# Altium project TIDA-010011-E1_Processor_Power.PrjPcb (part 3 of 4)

## Sheet TIDA-010011-E1_Processor_Power _Pg7.SchDoc: POINT OF LOAD
size 431 x 279 mm; Date: Not shown in title block; ApprovedBy: Not shown in title block; CheckedBy: Not shown in title block; Author: Not shown in title block; CompanyName: Not shown in title block; DrawnBy: Sreenivasa; Engineer: Not shown in title block; Organization: Not shown in title block; Address1: Not shown in title block; Address2: Not shown in title block; Address3: Not shown in title block; Address4: Not shown in title block; DocumentNumber: 1; Revision: Use project parameter SCH_Rev; SheetNumber: 7; SheetTotal: 12; PageSetup: Record=PageOptions¦CenterHorizontal=True¦CenterVertical=True¦PrintScale=0.62¦XCorrection=1.00¦YCorrection=1.00¦PrintKind=0¦BorderSize=5000000¦LeftOffset=0¦BottomOffset=0¦Orientation=2¦PaperLength=1000¦PaperWidth=1000¦Scale=100¦PaperSource=15¦PrintQuality=600¦MediaType=1¦DitherType=10¦PrintScaleMode=1¦PaperKind=Letter
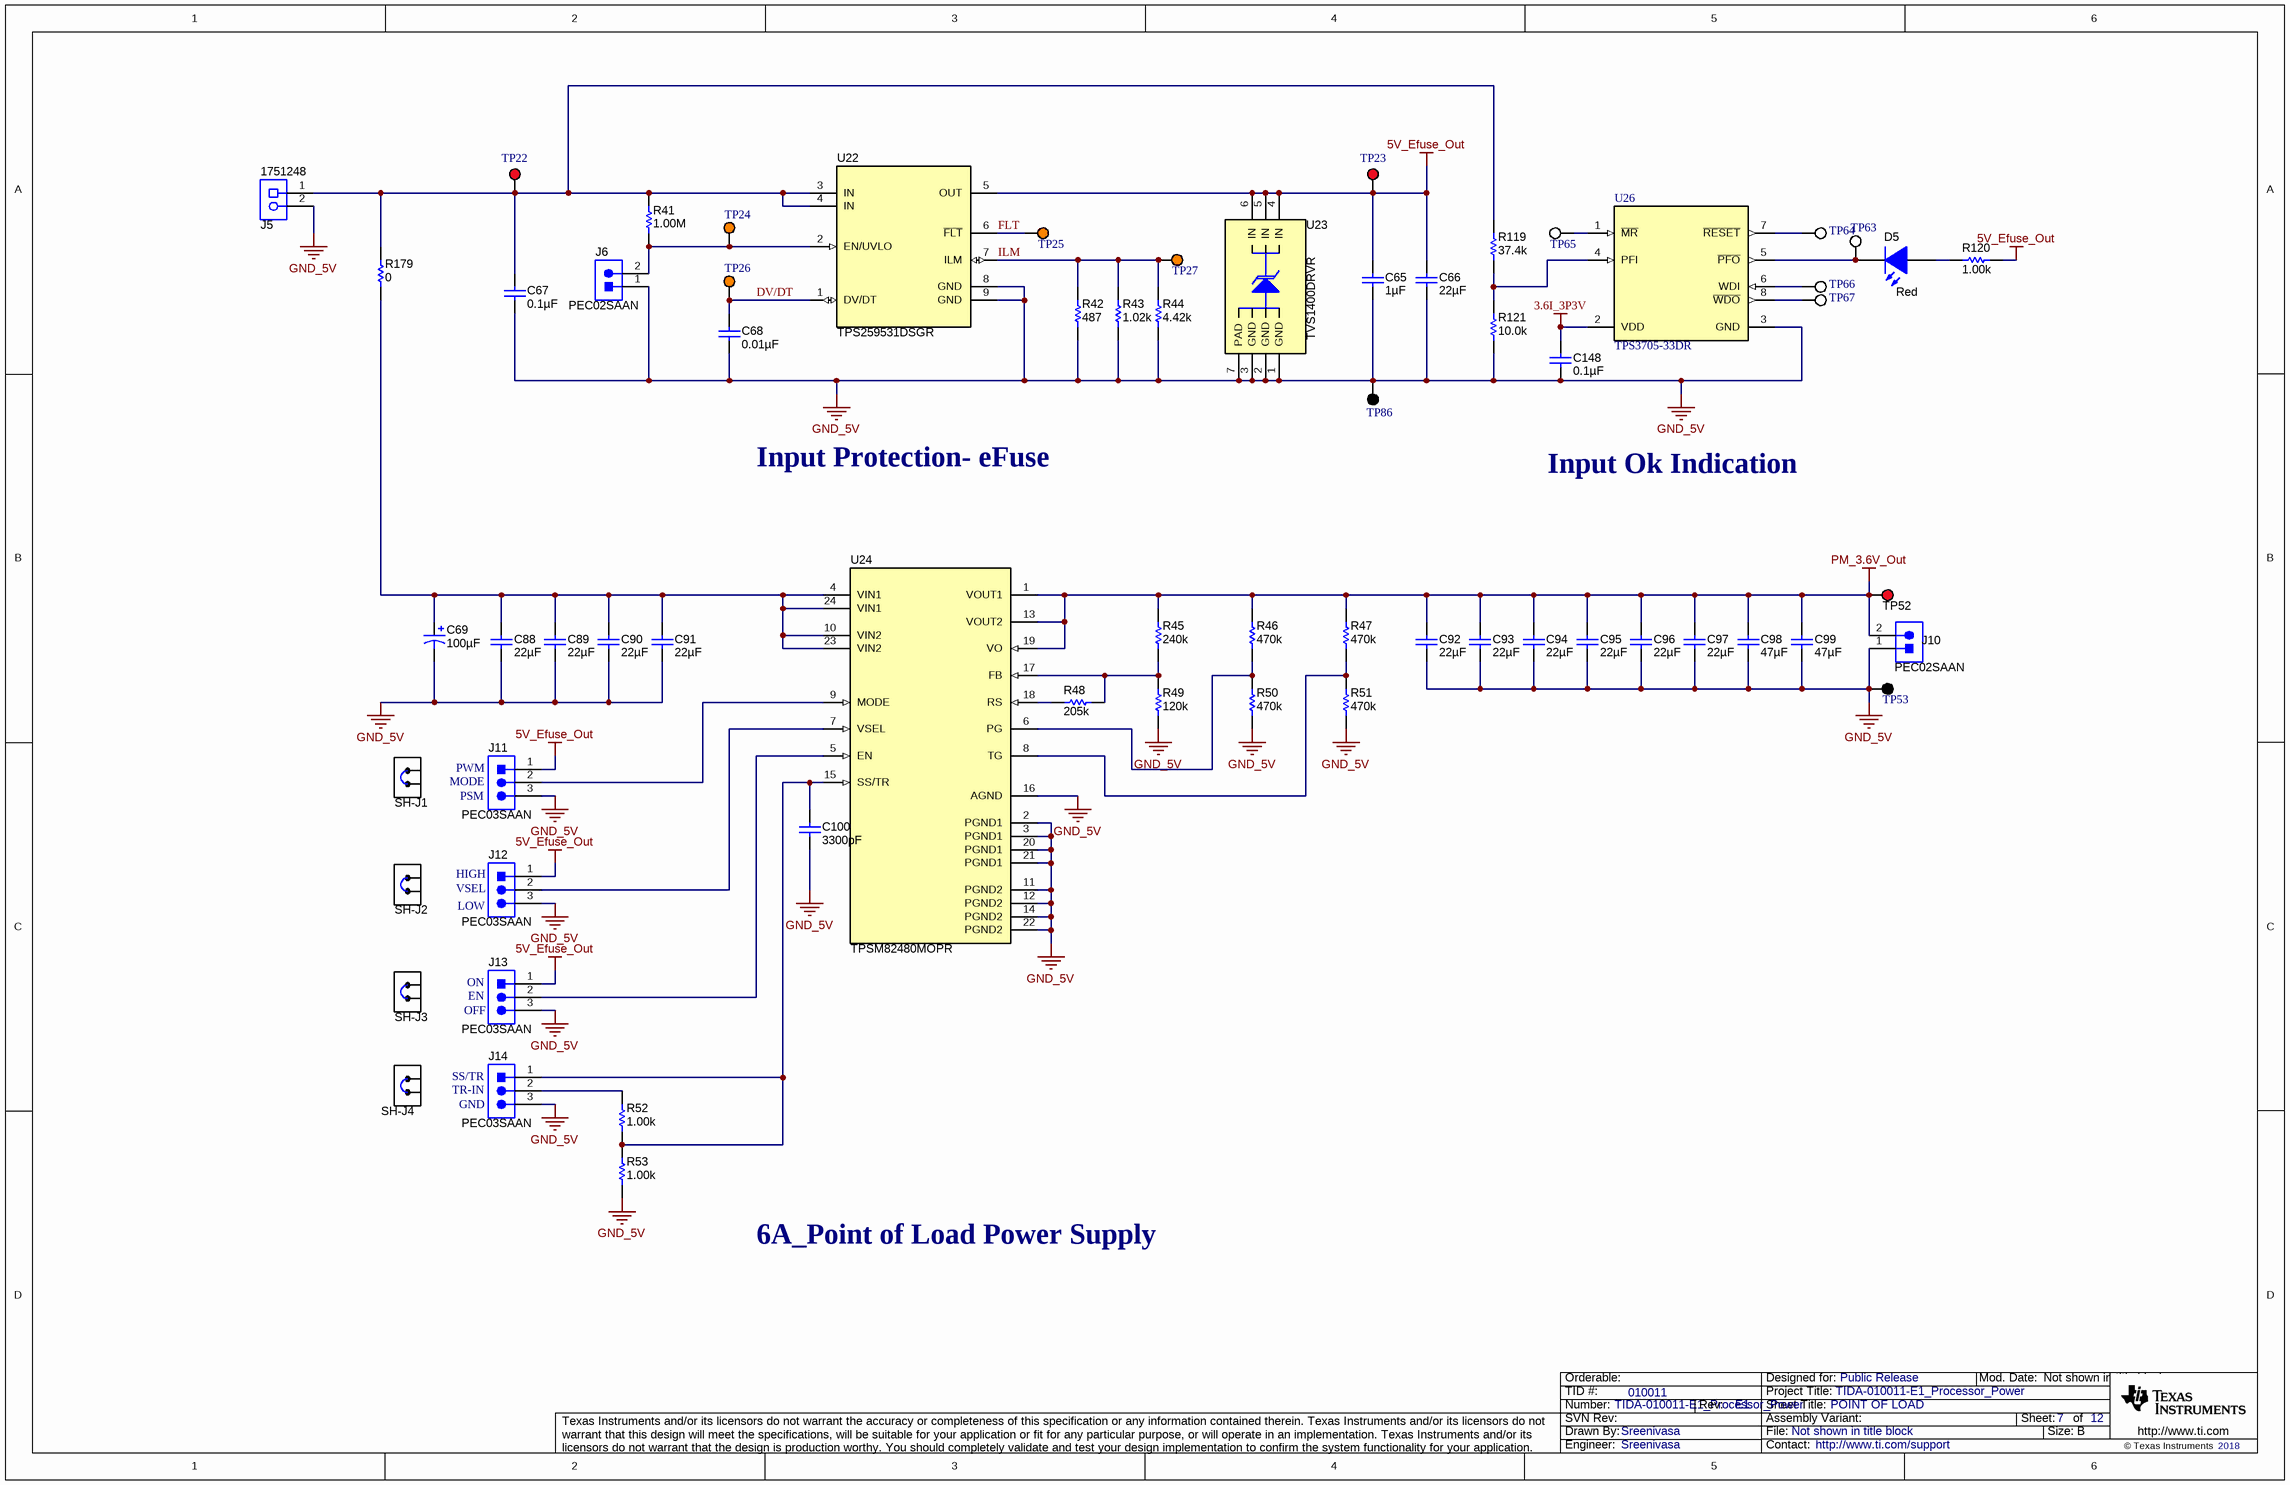
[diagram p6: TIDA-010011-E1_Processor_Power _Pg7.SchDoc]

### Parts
C65  ValueDisplayed: 1µF  [0805_HV]  (hidden comment: 08053D105KAT2A)
C66  ValueDisplayed: 22µF  [1812_280]  (hidden comment: C4532X5R1E226M250KA)
C67  ValueDisplayed: 0.1µF  [0603]  (hidden comment: GRM188R71E104KA01D)
C68  ValueDisplayed: 0.01µF  [0603]  (hidden comment: GRM188R71E103KA01D)
C69  ValueDisplayed: 100µF  [7343-43]  (hidden comment: 293D107X9020E2TE3)
C88  ValueDisplayed: 22µF  [0603]  (hidden comment: GRM188R61A226ME15D)
C89  ValueDisplayed: 22µF  [0603]  (hidden comment: GRM188R61A226ME15D)
C90  ValueDisplayed: 22µF  [0603]  (hidden comment: GRM188R61A226ME15D)
C91  ValueDisplayed: 22µF  [0603]  (hidden comment: GRM188R61A226ME15D)
C92  ValueDisplayed: 22µF  [0805_HV]  (hidden comment: GRM21BR61E226ME44L)
C93  ValueDisplayed: 22µF  [0805_HV]  (hidden comment: GRM21BR61E226ME44L)
C94  ValueDisplayed: 22µF  [0805_HV]  (hidden comment: GRM21BR61E226ME44L)
C95  ValueDisplayed: 22µF  [0805_HV]  (hidden comment: GRM21BR61E226ME44L)
C96  ValueDisplayed: 22µF  [0805_HV]  (hidden comment: GRM21BR61E226ME44L)
C97  ValueDisplayed: 22µF  [0805_HV]  (hidden comment: GRM21BR61E226ME44L)
C98  ValueDisplayed: 47µF  [CKG57N]  (hidden comment: CKG57NX7S1E476M500JH)
C99  ValueDisplayed: 47µF  [CKG57N]  (hidden comment: CKG57NX7S1E476M500JH)
C100  ValueDisplayed: 3300pF  [0603]  (hidden comment: GRM188R71H332KA01D)
C148  ValueDisplayed: 0.1µF  [0603]  (hidden comment: GRM188R71E104KA01D)
D5  value Red  [LED_LTST-C170_Red]  (hidden comment: CMP-0002829-2)
J5  1751248  [CONN_1751248]
J6  PEC02SAAN  [CONN_PEC02SAAN]
J10  PEC02SAAN  [CONN_PEC02SAAN]
J11  PEC03SAAN  [CONN_PEC03SAAN]
J12  PEC03SAAN  [CONN_PEC03SAAN]
J13  PEC03SAAN  [CONN_PEC03SAAN]
J14  PEC03SAAN  [CONN_PEC03SAAN]
R41  ValueDisplayed: 1.00M  [0603]  (hidden comment: CRCW06031M00FKEA)
R42  ValueDisplayed: 487  [0603]  (hidden comment: CRCW0603487RFKEA)
R43  ValueDisplayed: 1.02k  [0603]  (hidden comment: RC0603FR-071K02L)
R44  ValueDisplayed: 4.42k  [0603]  (hidden comment: CRCW06034K42FKEA)
R45  ValueDisplayed: 240k  [0603]  (hidden comment: RC0603FR-07240KL)
R46  ValueDisplayed: 470k  [0603]  (hidden comment: RC0603FR-07470KL)
R47  ValueDisplayed: 470k  [0603]  (hidden comment: RC0603FR-07470KL)
R48  ValueDisplayed: 205k  [0603]  (hidden comment: CRCW0603205KFKEA)
R49  ValueDisplayed: 120k  [0603]  (hidden comment: RC0603FR-07120KL)
R50  ValueDisplayed: 470k  [0603]  (hidden comment: RC0603FR-07470KL)
R51  ValueDisplayed: 470k  [0603]  (hidden comment: RC0603FR-07470KL)
R52  ValueDisplayed: 1.00k  [0603]  (hidden comment: RC0603FR-071KL)
R53  ValueDisplayed: 1.00k  [0603]  (hidden comment: RC0603FR-071KL)
R119  ValueDisplayed: 37.4k  [0603]  (hidden comment: CRCW060337K4FKEA)
R120  ValueDisplayed: 1.00k  [0603]  (hidden comment: ERJ-3EKF1001V)
R121  ValueDisplayed: 10.0k  [0603]  (hidden comment: CRCW060310K0FKEA)
R179  ValueDisplayed: 0  [0805_HV]  (hidden comment: CRCW08050000Z0EA)
SH-J1  881545-2  [TE_881545-2]  (value not drawn)  (mechanical)
SH-J2  881545-2  [TE_881545-2]  (value not drawn)  (mechanical)
SH-J3  881545-2  [TE_881545-2]  (value not drawn)  (mechanical)
SH-J4  881545-2  [TE_881545-2]  (value not drawn)  (mechanical)
TP22  5000  [Keystone5000]  (value not drawn)
TP23  5000  [Keystone5000]  (value not drawn)
TP24  5003  [Keystone5003]  (value not drawn)
TP25  5003  [Keystone5003]  (value not drawn)
TP26  5003  [Keystone5003]  (value not drawn)
TP27  5003  [Keystone5003]  (value not drawn)
TP52  (no value)  [Keystone5000]
TP53  5001  [Keystone5001]  (value not drawn)
TP63  5002  [Keystone5002]  (value not drawn)
TP64  5002  [Keystone5002]  (value not drawn)
TP65  5002  [Keystone5002]  (value not drawn)
TP66  5002  [Keystone5002]  (value not drawn)
TP67  5002  [Keystone5002]  (value not drawn)
TP86  5001  [Keystone5001]  (value not drawn)
U22  TPS259531DSGR  [DSG0008A]
U23  TVS1400DRVR  [DRV0006A]
U24  TPSM82480MOPR  [MOP0024A]
U26  TPS3705-33DR  [D0008A_N]

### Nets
3.6I_3P3V: C148.1 U26.2(VDD)
5V_Efuse_Out: C65.1 C66.1 J11.1 J12.1 J13.1 R120.2 TP23.1 U22.5(OUT) U23.4(IN) U23.5(IN) U23.6(IN)
GND_5V: C65.2 C66.2 C67.2 C68.2 C69.2(-) C88.2 C89.2 C90.2 C91.2 C92.2 C93.2 C94.2 C95.2 C96.2 C97.2 C98.2 C99.2 C100.1 C148.2 J5.2 J6.1 J10.1 J11.3 J12.3 J13.3 J14.3 R42.1 R43.1 R44.1 R49.1 R50.1 R51.1 R53.1 R121.1 TP53.1 TP86.1 U22.8(GND) U22.9(GND) U23.1(GND) U23.2(GND) U23.3(GND) U23.7(PAD) U24.2(PGND1) U24.3(PGND1) U24.11(PGND2) U24.12(PGND2) U24.14(PGND2) U24.16(AGND) U24.20(PGND1) U24.21(PGND1) U24.22(PGND2) U26.3(GND)
PM_3.6V_Out: C92.1 C93.1 C94.1 C95.1 C96.1 C97.1 C98.1 C99.1 J10.2 R45.2 R46.2 R47.2 TP52.1 U24.1(VOUT1) U24.13(VOUT2) U24.19(VO)
DV/DT: C68.1 TP26.1 U22.1(DV/DT)
FLT: TP25.1 U22.6(~{FLT})
ILM: R42.2 R43.2 R44.2 TP27.1 U22.7(ILM)
NetC67_1: C67.1 J5.1 R41.2 R119.2 R179.1 TP22.1 U22.3(IN) U22.4(IN)
NetC69_1: C69.1(+) C88.1 C89.1 C90.1 C91.1 R179.2 U24.4(VIN1) U24.10(VIN2) U24.23(VIN2) U24.24(VIN1)
NetC100_2: C100.2 J14.1 R52.1 R53.2 U24.15(SS/TR)
NetD5_1: D5.1(A) R120.1
NetD5_2: D5.2(K) TP63.1 U26.5(~{PFO})
NetJ6_2: J6.2 R41.1 TP24.1 U22.2(EN/UVLO)
NetJ11_2: J11.2 U24.9(MODE)
NetJ12_2: J12.2 U24.7(VSEL)
NetJ13_2: J13.2 U24.5(EN)
NetJ14_2: J14.2 R52.2
NetR45_1: R45.1 R48.2 R49.2 U24.17(FB)
NetR46_1: R46.1 R50.2 U24.6(PG)
NetR47_1: R47.1 R51.2 U24.8(TG)
NetR48_1: R48.1 U24.18(RS)
NetR119_1: R119.1 R121.2 U26.4(PFI)
NetTP64_1: TP64.1 U26.7(~{RESET})
NetTP65_1: TP65.1 U26.1(~{MR})
NetTP66_1: TP66.1 U26.6(WDI)
NetTP67_1: TP67.1 U26.8(~{WDO})

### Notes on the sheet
- Input Protection- eFuse
- Input Ok Indication
- MODE
- PWM
- PSM
- HIGH
- VSEL
- LOW
- (near J13) OFF
- (near J13) ON
- (near J13) EN
- SS/TR
- TR-IN
- GND
- 6A_Point of Load Power Supply

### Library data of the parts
C65 = 08053D105KAT2A: CAP, CERM, 1 µF, 25 V,+/- 10%, X5R, 0805; Manufacturer: AVX; Polarized: N; CompType: Capacitor; Value: 1uF; U/M: EA; Cap_F: 0.000001; Tolerance_%: 10; ESR_ohm: 0.012; Value1: 0.012 ohm; VDC_V: 25; Value2: 25V; TaMin_C: -55; TaMax_C: 85; Cap_Case: 0805; SizeArea_mm2: 2.5; SizeAreaWB_mm2: 6.75; SizeX_mm: 2; SizeY_mm: 1.25; SizeZ_mm: 1.45; AEC Category: Q200; Green_Lifecycle: Active; Green_REACh: Passed
C66 = C4532X5R1E226M250KA: CAP, CERM, 22 µF, 25 V,+/- 20%, X5R, 1812; Manufacturer: TDK; Polarized: N; CompType: Capacitor; Value: 22uF; U/M: EA; Cap_F: 0.000022; Tolerance_%: 20; ESR_ohm: 0.002434; Value1: 0.002434 ohm; VDC_V: 25; Value2: 25V; IRMS_A: 4.91649; TaMin_C: -55; TaMax_C: 85; Cap_Case: 1812; SizeArea_mm2: 14.4; SizeAreaWB_mm2: 23.1; SizeX_mm: 4.5; SizeY_mm: 3.2; SizeZ_mm: 2.8; AEC Category: Q200
C67 C148 = GRM188R71E104KA01D: CAP, CERM, 0.1 µF, 25 V,+/- 10%, X7R, 0603; Manufacturer: MuRata; Polarized: N; CompType: Capacitor; Value: 0.1uF; U/M: EA; Cap_F: 0.0000001; Tolerance_%: 10; VDC_V: 25; Value2: 25V; TaMin_C: -55; TaMax_C: 125; SizeArea_mm2: 1.28; SizeAreaWB_mm2: 4.68; SizeX_mm: 1.6; SizeY_mm: 0.8; SizeZ_mm: 1; AEC Category: Q200; Green_Lifecycle: Active; Green_REACh: Passed
C68 = GRM188R71E103KA01D: CAP, CERM, 0.01 µF, 25 V,+/- 10%, X7R, 0603; Manufacturer: MuRata; Polarized: N; CompType: Capacitor; Value: 0.01uF; U/M: EA; Cap_F: 0.00000001; Tolerance_%: 10; VDC_V: 25; Value2: 25V; TaMin_C: -55; TaMax_C: 125; SizeArea_mm2: 1.28; SizeAreaWB_mm2: 4.68; SizeX_mm: 1.6; SizeY_mm: 0.8; SizeZ_mm: 1; AEC Category: Q200; Green_Lifecycle: Active; Green_REACh: Passed
C69 = 293D107X9020E2TE3: CAP, TA, 100 µF, 20 V, +/- 10%, 0.5 ohm, SMD; Manufacturer: Vishay-Sprague; Polarized: Y; CompType: Capacitor; Value: 100uF; U/M: EA; Cap_F: 0.0001; Tolerance_%: 10; Value1: 0.5 ohm; VDC_V: 20; Value2: 20V; ESR_ohm: 0.5; IRMS_A: 0.57; TaMin_C: -55; TaMax_C: 125; Cap_Case: E; SizeAreaWB_mm2: 58.59; SizeArea_mm2: 31.39; SizeX_mm: 7.3; SizeY_mm: 4.3; AEC Category: Q200
C88-C91 = GRM188R61A226ME15D: CAP, CERM, 22 µF, 10 V,+/- 20%, X5R, 0603; Manufacturer: MuRata; Polarized: N; CompType: Capacitor; Value: 22uF; U/M: EA; Cap_F: 0.000022; Tolerance_%: 20; VDC_V: 10; Value2: 10V; TaMin_C: -55; TaMax_C: 85; SizeArea_mm2: 1.28; SizeAreaWB_mm2: 4.68; SizeX_mm: 1.6; SizeY_mm: 0.8; SizeZ_mm: 1; AEC Category: Q200; Green_Lifecycle: Active; Green_REACh: Passed
C92-C97 = GRM21BR61E226ME44L: CAP, CERM, 22 µF, 25 V,+/- 20%, X5R, 0805; Manufacturer: MuRata; Polarized: N; CompType: Capacitor; Value: 22uF; U/M: EA; Cap_F: 0.000022; Tolerance_%: 20; VDC_V: 25; Value2: 25V; TaMin_C: -55; TaMax_C: 85; Cap_Case: 0805; SizeArea_mm2: 2.5; SizeAreaWB_mm2: 6.75; SizeX_mm: 2; SizeY_mm: 1.25; SizeZ_mm: 1.45; AEC Category: Q200; Green_Lifecycle: Active; Green_REACh: Passed
C98 C99 = CKG57NX7S1E476M500JH: CAP, CERM, 47 µF, 25 V,+/- 20%, X7S, 6x5x5mm; Manufacturer: TDK; Polarized: N; CompType: Capacitor; Value: 47uF; U/M: EA; Cap_F: 0.000047; Tolerance_%: 20; VDC_V: 25; Value2: 25V; TaMin_C: -55; TaMax_C: 125; Cap_Case: 2220; SizeArea_mm2: 30; SizeAreaWB_mm2: 56; SizeX_mm: 6; SizeY_mm: 5; SizeZ_mm: 5.5; AEC Category: Q200
C100 = GRM188R71H332KA01D: CAP, CERM, 3300 pF, 50 V,+/- 10%, X7R, 0603; Manufacturer: MuRata; Polarized: N; CompType: Capacitor; Value: 3300pF; U/M: EA; Cap_F: 0.0000000033; Tolerance_%: 10; VDC_V: 50; Value2: 50V; TaMin_C: -55; TaMax_C: 125; SizeArea_mm2: 1.28; SizeAreaWB_mm2: 4.68; SizeX_mm: 1.6; SizeY_mm: 0.8; SizeZ_mm: 1; AEC Category: Q200; Green_Lifecycle: Active; Green_REACh: Passed
D5 = CMP-0002829-2: LED, Red, SMD; PartNumber: LTST-C170KRKT; Manufacturer: Lite-On; Type: AlInGaP; Vf_V: 2V; Io_A: 20mA; Value1: W; SizeAreaWB_mm2: 6.75; SizeArea_mm2: 2.5; SizeX_mm: 2; SizeY_mm: 1.25; SizeZ_mm: 1.2; U/M: EA
J5 = 1751248: Conn Term Block, 2POS, 3.5mm, TH; Manufacturer: Phoenix Contact; CompType: Terminal Block; SymbolCreator: a0412235
J6 J10 = PEC02SAAN: Header, 100mil, 2x1, Tin, TH; Manufacturer: Sullins Connector Solutions; SymbolCreator: a0412235; Pitch_mm: 2.54; Gender: Male; Shrouded: N; Row_Count: 1; Current_A: 3; Voltage_V: 1800; Cert_UL: Y; Green_Lifecycle: Not Set; Green_REACh: Incomplete
J11-J14 = PEC03SAAN: Header, 100mil, 3x1, Tin, TH; Manufacturer: Sullins Connector Solutions; SymbolCreator: a0412235; Pitch_mm: 2.54; Gender: Male; Shrouded: N; Row_Count: 1; Current_A: 3; Voltage_V: 1800; Cert_UL: Y; Green_Lifecycle: Not Set; Green_REACh: Incomplete
R41 = CRCW06031M00FKEA: RES, 1.00 M, 1%, 0.1 W, 0603; Manufacturer: Vishay-Dale; CompType: Resistor; Value: 1.00Meg; Res_ohm: 1000000; Value_Code: 1M00; Tolerance_%: 1; Power_W: 0.1; Value2: 0.1W; VDC_V: 75; TempCo: 100 ppm/C; SizeArea_mm2: 1.28; SizeX_mm: 1.6; SizeY_mm: 0.8; EIA_Code: E96; U/M: EA; AEC Category: Q200; Green_Lifecycle: Active; Green_REACh: Passed
R42 = CRCW0603487RFKEA: RES, 487, 1%, 0.1 W, 0603; Manufacturer: Vishay-Dale; CompType: Resistor; Value: 487; Value_Code: 487R; Tolerance_%: 1; Power_W: 0.1; Value2: 0.1W; VDC_V: 75; TempCo: 100 ppm/C; SizeArea_mm2: 1.28; SizeX_mm: 1.6; SizeY_mm: 0.8; EIA_Code: E96; U/M: EA; AEC Category: Q200; Green_Lifecycle: Active; Green_REACh: Passed
R43 = RC0603FR-071K02L: RES, 1.02 k, 1%, 0.1 W, 0603; Manufacturer: Yageo America; CompType: Resistor; Value: 1.02k; Res_ohm: 1020; Value_Code: 1k02; Tolerance_%: 1; Power_W: 0.1; Value2: 0.1W; VDC_V: 150; TempCo: 200 ppm/C; SizeArea_mm2: 1.28; SizeX_mm: 1.6; SizeY_mm: 0.8; EIA_Code: E96; U/M: EA; AEC Category: Q200
R44 = CRCW06034K42FKEA: RES, 4.42 k, 1%, 0.1 W, 0603; Manufacturer: Vishay-Dale; CompType: Resistor; Value: 4.42k; Res_ohm: 4420; Value_Code: 4k42; Tolerance_%: 1; Power_W: 0.1; Value2: 0.1W; VDC_V: 75; TempCo: 100 ppm/C; SizeArea_mm2: 1.28; SizeX_mm: 1.6; SizeY_mm: 0.8; EIA_Code: E96; U/M: EA; AEC Category: Q200; Green_Lifecycle: Active; Green_REACh: Passed
R45 = RC0603FR-07240KL: RES, 240 k, 1%, 0.1 W, 0603; Manufacturer: Yageo America; CompType: Resistor; Value: 240k; Res_ohm: 240000; Tolerance_%: 1; Power_W: 0.1; Value2: 0.1W; VDC_V: 150; TempCo: 200 ppm/C; SizeArea_mm2: 1.28; SizeX_mm: 1.6; SizeY_mm: 0.8; U/M: EA; AEC Category: Q200; Green_Lifecycle: Active; Green_REACh: Passed
R46 R47 R50 R51 = RC0603FR-07470KL: RES, 470 k, 1%, 0.1 W, 0603; Manufacturer: Yageo America; CompType: Resistor; Value: 470k; Res_ohm: 470000; Tolerance_%: 1; Power_W: 0.1; Value2: 0.1W; VDC_V: 150; TempCo: 200 ppm/C; SizeArea_mm2: 1.28; SizeX_mm: 1.6; SizeY_mm: 0.8; U/M: EA; AEC Category: Q200; Green_Lifecycle: Active; Green_REACh: Passed
R48 = CRCW0603205KFKEA: RES, 205 k, 1%, 0.1 W, 0603; Manufacturer: Vishay-Dale; CompType: Resistor; Value: 205k; Res_ohm: 205000; Tolerance_%: 1; Power_W: 0.1; Value2: 0.1W; VDC_V: 75; TempCo: 100 ppm/C; SizeArea_mm2: 1.28; SizeX_mm: 1.6; SizeY_mm: 0.8; EIA_Code: E96; U/M: EA; AEC Category: Q200; Green_Lifecycle: Active; Green_REACh: Passed
R49 = RC0603FR-07120KL: RES, 120 k, 1%, 0.1 W, 0603; Manufacturer: Yageo America; CompType: Resistor; Value: 120k; Res_ohm: 120000; Tolerance_%: 1; Power_W: 0.1; Value2: 0.1W; VDC_V: 150; TempCo: 200 ppm/C; SizeArea_mm2: 1.28; SizeX_mm: 1.6; SizeY_mm: 0.8; U/M: EA; AEC Category: Q200
R52 R53 = RC0603FR-071KL: RES, 1.00 k, 1%, 0.1 W, 0603; Manufacturer: Yageo America; CompType: Resistor; Value: 1.00k; Res_ohm: 1000; Value_Code: 1k00; Tolerance_%: 1; Power_W: 0.1; Value2: 0.1W; VDC_V: 150; TempCo: 200 ppm/C; SizeArea_mm2: 1.28; SizeX_mm: 1.6; SizeY_mm: 0.8; EIA_Code: E96; U/M: EA; AEC Category: Q200; Green_Lifecycle: Active; Green_REACh: Passed
R119 = CRCW060337K4FKEA: RES, 37.4 k, 1%, 0.1 W, 0603; Manufacturer: Vishay-Dale; CompType: Resistor; Value: 37.4k; Res_ohm: 37400; Value_Code: 37k4; Tolerance_%: 1; Power_W: 0.1; Value2: 0.1W; VDC_V: 75; TempCo: 100 ppm/C; SizeArea_mm2: 1.28; SizeX_mm: 1.6; SizeY_mm: 0.8; EIA_Code: E96; U/M: EA; AEC Category: Q200; Green_Lifecycle: Active; Green_REACh: Passed
R120 = ERJ-3EKF1001V: RES, 1.00 k, 1%, 0.1 W, AEC-Q200 Grade 0, 0603; Manufacturer: Panasonic; CompType: Resistor; Value: 1.00k; Res_ohm: 1000; Value_Code: 1k00; Tolerance_%: 1; Power_W: 0.1; Value2: 0.1W; VDC_V: 75; TempCo: 100 ppm/C; SizeArea_mm2: 1.28; SizeX_mm: 1.6; SizeY_mm: 0.8; EIA_Code: E96; U/M: EA; AEC Category: Q200; AEC Qualified: Y; AEC Grade: 0; Green_Lifecycle: Active; Green_REACh: Passed
R121 = CRCW060310K0FKEA: RES, 10.0 k, 1%, 0.1 W, 0603; Manufacturer: Vishay-Dale; CompType: Resistor; Value: 10.0k; Res_ohm: 10000; Value_Code: 10k0; Tolerance_%: 1; Power_W: 0.1; Value2: 0.1W; VDC_V: 75; TempCo: 100 ppm/C; SizeArea_mm2: 1.28; SizeX_mm: 1.6; SizeY_mm: 0.8; EIA_Code: E96; U/M: EA; AEC Category: Q200; Green_Lifecycle: Active; Green_REACh: Passed
R179 = CRCW08050000Z0EA: RES, 0, 5%, 0.125 W, 0805; Manufacturer: Vishay-Dale; CompType: Resistor; Value: 0; Value_Code: 0000; Tolerance_%: 5; Power_W: 0.125; Value2: 0.125W; VDC_V: 150; TempCo: 200 ppm/C; SizeArea_mm2: 2.5; SizeX_mm: 2; SizeY_mm: 1.25; SizeZ_mm: 1.45; EIA_Code: E24; U/M: EA; AEC Category: Q200; Green_Lifecycle: Active; Green_REACh: Passed
SH-J1-SH-J4 = 881545-2: Shunt, 100mil, Gold plated, Black; Manufacturer: TE Connectivity
TP22 TP23 = 5000: Test Point, Miniature, Red, TH; Manufacturer: Keystone; CompType: Test Point Loop; ContactFinish: Silver; Green_Lifecycle: Active; Green_REACh: Passed
TP24-TP27 = 5003: Test Point, Miniature, Orange, TH; Manufacturer: Keystone; CompType: Test Point Loop; ContactFinish: Silver; Green_Lifecycle: Active; Green_REACh: Passed
TP52 = 5000: Test Point, Miniature, Red, TH; Manufacturer: Keystone; CompType: Test Point Loop; ContactFinish: Silver
TP53 TP86 = 5001: Test Point, Miniature, Black, TH; Manufacturer: Keystone; CompType: Test Point Loop; ContactFinish: Silver; Green_Lifecycle: Active; Green_REACh: Passed
TP63-TP67 = 5002: Test Point, Miniature, White, TH; Manufacturer: Keystone; CompType: Test Point Loop; ContactFinish: Silver; Green_Lifecycle: Active; Green_REACh: Passed
U22 = CMP-0013453-3: 12V eFuse with Over Voltage Protection, DSG0008A (WSON-8); Alternate PartNumber: TPS259531DSGT; Manufacturer: Texas Instruments; SizeZ_mm: 0.8; SizeX_mm: 2; SizeArea_mm2: 4; CompType: IC; U/M: EA; SizeAreaWB_mm2: 9
U23 = CMP-0077836-1: 14-V Precision Surge Protection Clamp, DRV0006A (WSON-6); Alternate Manufacturer: Texas Instruments; SizeAreaWB_mm2: 9.0; SizeZ_mm: 0.8; SizeX_mm: 2.0; SizeArea_mm2: 4.0; CompType: IC; AEC Qualified: N; AEC Category: Q200
U24 = CMP-0013542-5: 5.5-V Input, 6-A, Step-Down Converter with Integrated Inductor, MOP0024A (QFM-24); Manufacturer: Texas Instruments; SizeZ_mm: 1.55; SizeX_mm: 3.6; SizeY_mm: 7.9; SizeArea_mm2: 28.44; CompType: IC; U/M: EA; SizeAreaWB_mm2: 55.44; AEC Category: Q200; AEC Qualified: N
U26 = CMP-0032306-1: Processor Supervisory Circuit with Power-Fail, 2 Supply Monitored, -40 to 85 degC, 8-pin SOIC (D), Green (RoHS & no Sb/Br); Manufacturer: Texas Instruments; Iq(Typ)(uA): 30; VCC(Min)(V): 2; Watchdog Timer WDI(sec): 1.6; Time Delay(ms): 200; Reset Threshold Accuracy(%): 1.9; VCC(Max)(V): 3.3; Threshold Voltage 2 (typ)(Typ)(V): Adjustable; SubFamily: Supervisor and Reset IC; Output Driver Type / Reset Output: Active-low, Push-pull; Rating: Catalog; Threshold Voltage 1 (typ)(Typ)(V): 2.93

## Sheet TIDA-010011-E1_Processor_Power _Pg8.SchDoc: 5V POWER MODULE
size 431 x 279 mm; Date: Not shown in title block; ApprovedBy: Not shown in title block; CheckedBy: Not shown in title block; Author: Not shown in title block; CompanyName: Not shown in title block; DrawnBy: Sreenivasa; Engineer: Not shown in title block; Organization: Not shown in title block; Address1: Not shown in title block; Address2: Not shown in title block; Address3: Not shown in title block; Address4: Not shown in title block; DocumentNumber: 1; Revision: Use project parameter SCH_Rev; SheetNumber: 8; SheetTotal: 12; PageSetup: Record=PageOptions¦CenterHorizontal=True¦CenterVertical=True¦PrintScale=0.62¦XCorrection=1.00¦YCorrection=1.00¦PrintKind=0¦BorderSize=5000000¦LeftOffset=0¦BottomOffset=0¦Orientation=2¦PaperLength=1000¦PaperWidth=1000¦Scale=100¦PaperSource=15¦PrintQuality=600¦MediaType=1¦DitherType=10¦PrintScaleMode=1¦PaperKind=Letter
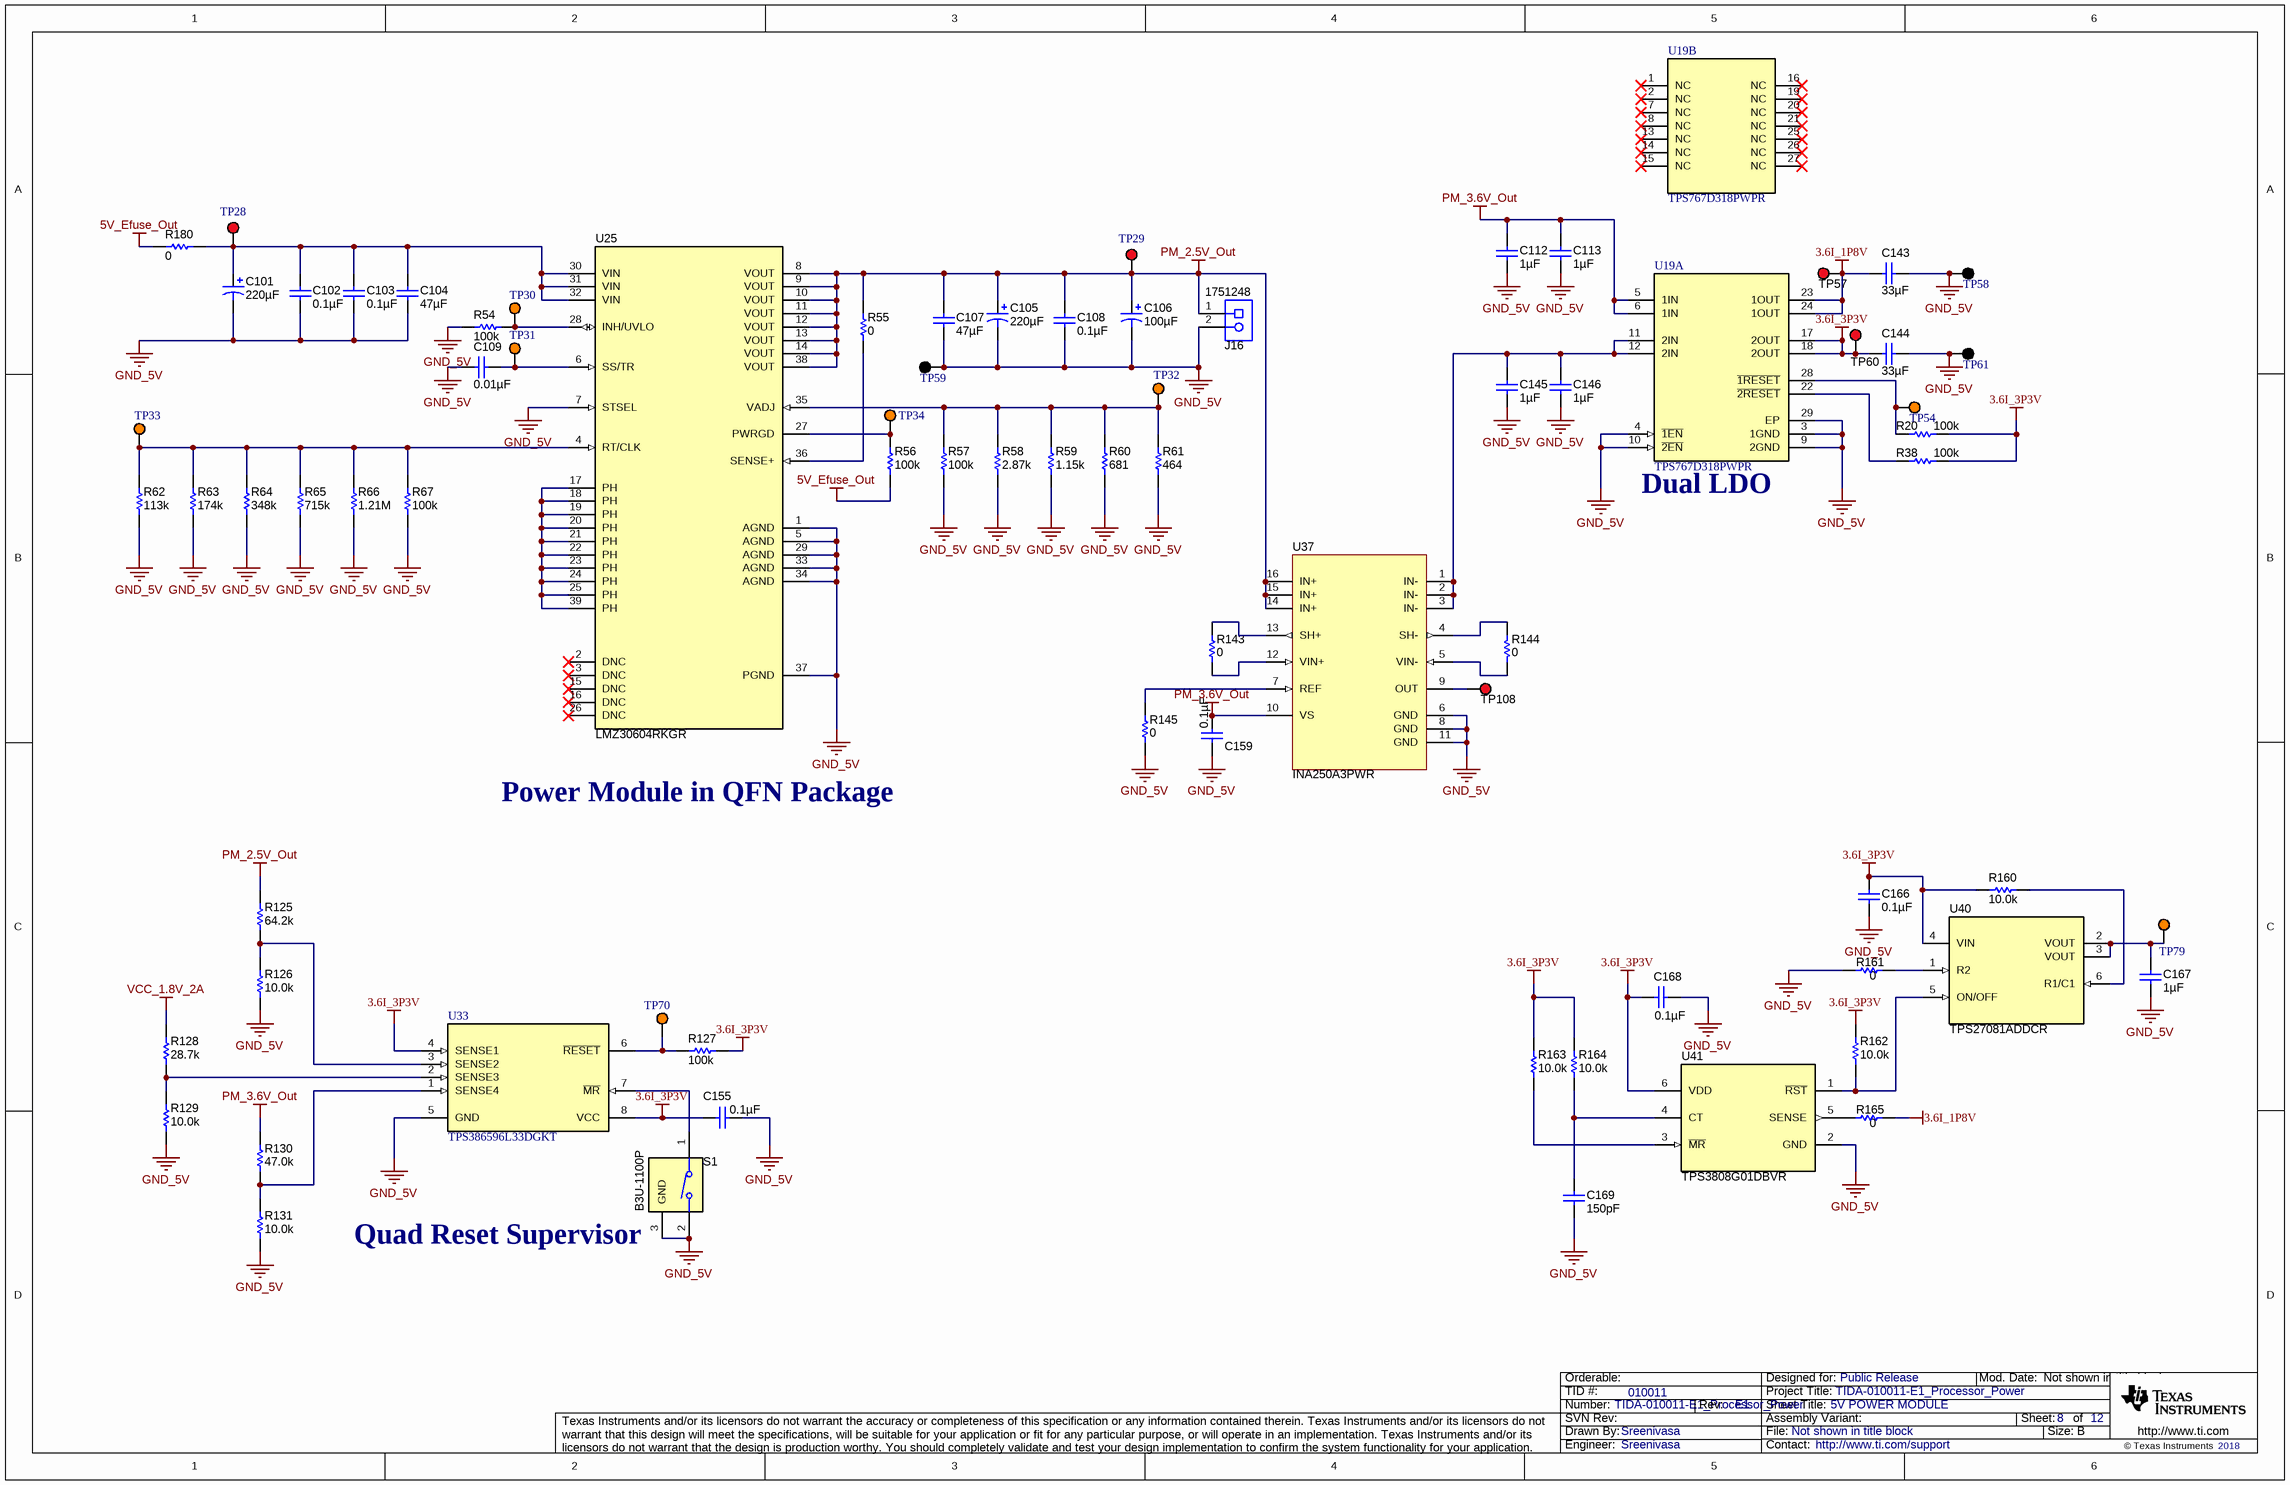
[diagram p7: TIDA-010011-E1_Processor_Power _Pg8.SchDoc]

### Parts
C101  ValueDisplayed: 220µF  [7343-30]  (hidden comment: 10TPE220ML)
C102  ValueDisplayed: 0.1µF  [1206]  (hidden comment: C1206C104J5RACTU)
C103  ValueDisplayed: 0.1µF  [1206]  (hidden comment: C1206C104J5RACTU)
C104  ValueDisplayed: 47µF  [1210_270]  (hidden comment: GRM32ER61A476KE20L)
C105  ValueDisplayed: 220µF  [7343-30]  (hidden comment: 10TPE220ML)
C106  ValueDisplayed: 100µF  [7343-20]  (hidden comment: 6TPE100MI)
C107  ValueDisplayed: 47µF  [1210_270]  (hidden comment: GRM32ER60J476ME20L)
C108  ValueDisplayed: 0.1µF  [1206]  (hidden comment: C1206C104J5RACTU)
C109  ValueDisplayed: 0.01µF  [0603]  (hidden comment: GRM188R71E103KA01D)
C112  ValueDisplayed: 1µF  [0603]  (hidden comment: UMK107AB7105KA-T)
C113  ValueDisplayed: 1µF  [0603]  (hidden comment: UMK107AB7105KA-T)
C143  ValueDisplayed: 33µF  [0805_HV]  (hidden comment: C2012X5R1A336M125AC)
C144  ValueDisplayed: 33µF  [0805_HV]  (hidden comment: C2012X5R1A336M125AC)
C145  ValueDisplayed: 1µF  [0603]  (hidden comment: UMK107AB7105KA-T)
C146  ValueDisplayed: 1µF  [0603]  (hidden comment: UMK107AB7105KA-T)
C155  ValueDisplayed: 0.1µF  [0603L]  (hidden comment: GRM188R71H104KA93D)
C159  ValueDisplayed: 0.1µF  [0603L]  (hidden comment: GRM188R71H104KA93D)
C166  ValueDisplayed: 0.1µF  [0603M]  (hidden comment: 06033C104JAT2A)
C167  ValueDisplayed: 1µF  [0603]  (hidden comment: UMK107AB7105KA-T)
C168  ValueDisplayed: 0.1µF  [0603M]  (hidden comment: 06033C104JAT2A)
C169  ValueDisplayed: 150pF  [0603]  (hidden comment: 06035A151JAT2A)
J16  1751248  [CONN_1751248]
R20  ValueDisplayed: 100k  [0603]  (hidden comment: RC0603FR-07100KL)
R38  ValueDisplayed: 100k  [0603]  (hidden comment: RC0603FR-07100KL)
R54  ValueDisplayed: 100k  [0402]  (hidden comment: CRCW0402100KFKED)
R55  ValueDisplayed: 0  [0603]  (hidden comment: ERJ-3GEY0R00V)
R56  ValueDisplayed: 100k  [0603]  (hidden comment: RC0603FR-07100KL)
R57  ValueDisplayed: 100k  [0603]  (hidden comment: RC0603FR-07100KL)
R58  ValueDisplayed: 2.87k  [0603]  (hidden comment: CRCW06032K87FKEA)
R59  ValueDisplayed: 1.15k  [0603]  (hidden comment: CRCW06031K15FKEA)
R60  ValueDisplayed: 681  [0603]  (hidden comment: CRCW0603681RFKEA)
R61  ValueDisplayed: 464  [0603]  (hidden comment: CRCW0603464RFKEA)
R62  ValueDisplayed: 113k  [0603]  (hidden comment: CRCW0603113KFKEA)
R63  ValueDisplayed: 174k  [0603]  (hidden comment: CRCW0603174KFKEA)
R64  ValueDisplayed: 348k  [0603]  (hidden comment: CRCW0603348KFKEA)
R65  ValueDisplayed: 715k  [0603]  (hidden comment: CRCW0603715KFKEA)
R66  ValueDisplayed: 1.21M  [0603]  (hidden comment: CRCW06031M21FKEA)
R67  ValueDisplayed: 100k  [0603]  (hidden comment: RC0603FR-07100KL)
R125  ValueDisplayed: 64.2k  [0603]  (hidden comment: RT0603BRD0764K2L)
R126  ValueDisplayed: 10.0k  [0603]  (hidden comment: ERJ-3EKF1002V)
R127  ValueDisplayed: 100k  [0603]  (hidden comment: RG1608P-104-B-T5)
R128  ValueDisplayed: 28.7k  [0603]  (hidden comment: CRCW060328K7FKEA)
R129  ValueDisplayed: 10.0k  [0603]  (hidden comment: ERJ-3EKF1002V)
R130  ValueDisplayed: 47.0k  [0603]  (hidden comment: RC0603FR-0747KL)
R131  ValueDisplayed: 10.0k  [0603]  (hidden comment: ERJ-3EKF1002V)
R143  ValueDisplayed: 0  [0603]  (hidden comment: ERJ-3GEY0R00V)
R144  ValueDisplayed: 0  [0603]  (hidden comment: ERJ-3GEY0R00V)
R145  ValueDisplayed: 0  [0603]  (hidden comment: ERJ-3GEY0R00V)
R160  value 10.0k  [0402M]  (hidden comment: CRCW040210K0FKED)
R161  value 0  [0603]  (hidden comment: CRCW06030000Z0EA)
R162  value 10.0k  [0402M]  (hidden comment: CRCW040210K0FKED)
R163  value 10.0k  [0402M]  (hidden comment: CRCW040210K0FKED)
R164  value 10.0k  [0402M]  (hidden comment: CRCW040210K0FKED)
R165  value 0  [0603]  (hidden comment: CRCW06030000Z0EA)
R180  ValueDisplayed: 0  [0805_HV]  (hidden comment: CRCW08050000Z0EA)
S1  B3U-1100P  [SW_B3U-1100P]
TP28  5000  [Keystone5000]  (value not drawn)
TP29  5000  [Keystone5000]  (value not drawn)
TP30  5003  [Keystone5003]  (value not drawn)
TP31  5003  [Keystone5003]  (value not drawn)
TP32  5003  [Keystone5003]  (value not drawn)
TP33  5003  [Keystone5003]  (value not drawn)
TP34  5003  [Keystone5003]  (value not drawn)
TP54  5003  [Keystone5003]  (value not drawn)
TP57  (no value)  [Keystone5000]
TP58  5001  [Keystone5001]  (value not drawn)
TP59  5001  [Keystone5001]  (value not drawn)
TP60  (no value)  [Keystone5000]
TP61  5001  [Keystone5001]  (value not drawn)
TP70  5003  [Keystone5003]  (value not drawn)
TP79  5003  [Keystone5003]  (value not drawn)
TP108  (no value)  [Keystone5000]
U19  TPS767D318PWPR  [PWP0028D_L]  (parts A,B of 2)
U25  LMZ30604RKGR  [RKG0039A]
U33  TPS386596L33DGKT  [DGK0008A_N]
U37  INA250A3PWR  [PW0016A_N]
U40  TPS27081ADDCR  [DDC0006A_N]
U41  TPS3808G01DBVR  [DBV0006A_N]

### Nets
3.6I_1P8V: C143.1 R165.1 TP57.1 U19.23(1OUT) U19.24(1OUT)
3.6I_3P3V: C144.1 C155.2 C166.1 C168.2 R20.1 R38.1 R127.1 R160.2 R162.2 R163.2 R164.2 TP60.1 U19.17(2OUT) U19.18(2OUT) U33.4(SENSE1) U33.8(VCC) U40.4(VIN) U41.6(VDD)
5V_Efuse_Out: R56.1 R180.2
GND_5V: C101.2(-) C102.2 C103.2 C104.2 C105.2(-) C106.2(-) C107.2 C108.2 C109.1 C112.2 C113.2 C143.2 C144.2 C145.2 C146.2 C155.1 C159.2 C166.2 C167.2 C168.1 C169.2 J16.2 R54.1 R57.1 R58.1 R59.1 R60.1 R61.1 R62.1 R63.1 R64.1 R65.1 R66.1 R67.1 R126.1 R129.1 R131.1 R145.2 R161.2 S1.2 S1.3(GND) TP58.1 TP59.1 TP61.1 U19.3(1GND) U19.4(~{1EN}) U19.9(2GND) U19.10(~{2EN}) U19.29(EP) U25.1(AGND) U25.5(AGND) U25.7(STSEL) U25.29(AGND) U25.33(AGND) U25.34(AGND) U25.37(PGND) U33.5(GND) U37.6(GND) U37.8(GND) U37.11(GND) U41.2(GND)
PM_2.5V_Out: C105.1(+) C106.1(+) C107.1 C108.1 J16.1 R55.2 R125.2 TP29.1 U25.8(VOUT) U25.9(VOUT) U25.10(VOUT) U25.11(VOUT) U25.12(VOUT) U25.13(VOUT) U25.14(VOUT) U25.38(VOUT) U37.14(IN+) U37.15(IN+) U37.16(IN+)
PM_3.6V_Out: C112.1 C113.1 C159.1 R130.2 U19.5(1IN) U19.6(1IN) U37.10(VS)
VCC_1.8V_2A: R128.2
NetC101_1: C101.1(+) C102.1 C103.1 C104.1 R180.1 TP28.1 U25.30(VIN) U25.31(VIN) U25.32(VIN)
NetC109_2: C109.2 TP31.1 U25.6(SS/TR)
NetC145_1: C145.1 C146.1 U19.11(2IN) U19.12(2IN) U37.1(IN-) U37.2(IN-) U37.3(IN-)
NetC167_1: C167.1 TP79.1 U40.2(VOUT) U40.3(VOUT)
NetC169_1: C169.1 R164.1 U41.4(CT)
NetR20_2: R20.2 TP54.1 U19.28(~{1RESET})
NetR38_2: R38.2 U19.22(~{2RESET})
NetR54_2: R54.2 TP30.1 U25.28(INH/UVLO)
NetR55_1: R55.1 U25.36(SENSE+)
NetR56_2: R56.2 TP34.1 U25.27(PWRGD)
NetR57_2: R57.2 R58.2 R59.2 R60.2 R61.2 TP32.1 U25.35(VADJ)
NetR62_2: R62.2 R63.2 R64.2 R65.2 R66.2 R67.2 TP33.1 U25.4(RT/CLK)
NetR125_1: R125.1 R126.2 U33.3(SENSE2)
NetR127_2: R127.2 TP70.1 U33.6(~{RESET})
NetR128_1: R128.1 R129.2 U33.2(SENSE3)
NetR130_1: R130.1 R131.2 U33.1(SENSE4)
NetR143_1: R143.1 U37.13(SH+)
NetR143_2: R143.2 U37.12(VIN+)
NetR144_1: R144.1 U37.4(SH-)
NetR144_2: R144.2 U37.5(VIN-)
NetR145_1: R145.1 U37.7(REF)
NetR160_1: R160.1 U40.6(R1/C1)
NetR161_1: R161.1 U40.1(R2)
NetR162_1: R162.1 U40.5(ON/OFF) U41.1(~{RST})
NetR163_1: R163.1 U41.3(~{MR})
NetR165_2: R165.2 U41.5(SENSE)
NetS1_1: S1.1 U33.7(~{MR})
NetTP108_1: TP108.1 U37.9(OUT)
NetU25_17: U25.17(PH) U25.18(PH) U25.19(PH) U25.20(PH) U25.21(PH) U25.22(PH) U25.23(PH) U25.24(PH) U25.25(PH) U25.39(PH)

Not connected (* = marked no-connect by the designer): U19 1(NC)* 2(NC)* 7(NC)* 8(NC)* 13(NC)* 14(NC)* 15(NC)* 16(NC)* 19(NC)* 20(NC)* 21(NC)* 25(NC)* 26(NC)* 27(NC)*; U25 2(DNC)* 3(DNC)* 15(DNC)* 16(DNC)* 26(DNC)*

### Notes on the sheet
- (near U19) Dual LDO
- Power Module in QFN Package
- (near S1) Quad Reset Supervisor

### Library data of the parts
C101 C105 = 10TPE220ML: CAP, Tantalum Polymer, 220 µF, 10 V,+/- 20%, 0.025 ohm, 7343-30 SMD; Manufacturer: Panasonic; Polarized: Y; CompType: Capacitor; Value: 220uF; U/M: EA; Cap_F: 0.00022; Tolerance_%: 20; VDC_V: 10; Value2: 10V; ESR_ohm: 0.025; IRMS_A: 2.4; TaMin_C: -55; TaMax_C: 105; SizeAreaWB_mm2: 58.59; SizeArea_mm2: 31.39; SizeX_mm: 7.3; SizeY_mm: 4.3; SizeZ_mm: 3; AEC Category: Q200; AEC Qualified: N; Green_Lifecycle: Active; Green_REACh: Passed
C102 C103 C108 = C1206C104J5RACTU: CAP, CERM, 0.1 µF, 50 V,+/- 5%, X7R, 1206; Manufacturer: Kemet; Polarized: N; CompType: Capacitor; Value: 0.1uF; U/M: EA; Cap_F: 0.0000001; Tolerance_%: 5; ESR_ohm: 0.059; Value1: 0.059 ohm; VDC_V: 50; Value2: 50V; IRMS_A: 1.2; TaMin_C: -55; TaMax_C: 125; SizeArea_mm2: 5.12; SizeAreaWB_mm2: 10.92; SizeX_mm: 3.2; SizeY_mm: 1.6; SizeZ_mm: 1.35; AEC Category: Q200; Green_Lifecycle: Active; Green_REACh: Passed
C104 = GRM32ER61A476KE20L: CAP, CERM, 47 µF, 10 V,+/- 10%, X5R, 1210; Manufacturer: MuRata; Polarized: N; CompType: Capacitor; Value: 47uF; U/M: EA; Cap_F: 0.000047; Tolerance_%: 10; ESR_ohm: 0.001; Value1: 0.001 ohm; Value2: 10V; TaMin_C: -55; TaMax_C: 85; Cap_Case: 1210; SizeArea_mm2: 8; SizeAreaWB_mm2: 14.7; SizeX_mm: 3.2; SizeY_mm: 2.5; SizeZ_mm: 2.7; AEC Category: Q200; Green_Lifecycle: Active; Green_REACh: Passed
C106 = 6TPE100MI: CAP, Tantalum Polymer, 100 µF, 6.3 V,+/- 20%, 0.018 ohm, 7343-20 SMD; Manufacturer: Panasonic; Polarized: Y; CompType: Capacitor; Value: 100uF; U/M: EA; Cap_F: 0.0001; Tolerance_%: 20; VDC_V: 6.3; Value2: 6.3V; ESR_ohm: 0.018; IRMS_A: 2.8; TaMin_C: -55; TaMax_C: 105; Cap_Case: D; SizeAreaWB_mm2: 58.59; SizeArea_mm2: 31.39; SizeX_mm: 7.3; SizeY_mm: 4.3; SizeZ_mm: 2; AEC Category: Q200; AEC Qualified: N
C107 = GRM32ER60J476ME20L: CAP, CERM, 47 µF, 6.3 V,+/- 20%, X5R, 1210; Manufacturer: MuRata; Polarized: N; CompType: Capacitor; Value: 47uF; U/M: EA; Cap_F: 0.000047; Tolerance_%: 20; ESR_ohm: 0.003; Value1: 0.003 ohm; VDC_V: 6.3; Value2: 6.3V; TaMin_C: -55; TaMax_C: 85; Cap_Case: 1210; SizeArea_mm2: 8; SizeAreaWB_mm2: 14.7; SizeX_mm: 3.2; SizeY_mm: 2.5; SizeZ_mm: 2.7; AEC Category: Q200; Green_Lifecycle: Active; Green_REACh: Passed
C109 = GRM188R71E103KA01D: as C68 on sheet TIDA-010011-E1_Processor_Power _Pg7
C112 C113 C145 C146 C167 = UMK107AB7105KA-T: CAP, CERM, 1 µF, 50 V,+/- 10%, X7R, 0603; Manufacturer: Taiyo Yuden; Polarized: N; CompType: Capacitor; Value: 1uF; U/M: EA; Cap_F: 0.000001; Tolerance_%: 10; VDC_V: 50; Value2: 50V; TaMin_C: -55; TaMax_C: 125; SizeArea_mm2: 1.28; SizeAreaWB_mm2: 4.68; SizeX_mm: 1.6; SizeY_mm: 0.8; SizeZ_mm: 1; AEC Category: Q200; Green_Lifecycle: Active; Green_REACh: Passed
C143 C144 = C2012X5R1A336M125AC: CAP, CERM, 33 µF, 10 V,+/- 20%, X5R, 0805; Manufacturer: TDK; Polarized: N; CompType: Capacitor; Value: 33uF; U/M: EA; Cap_F: 0.000033; Tolerance_%: 20; ESR_ohm: 0.001694; Value1: 0.001694 ohm; VDC_V: 10; Value2: 10V; IRMS_A: 5.01281; TaMin_C: -55; TaMax_C: 85; Cap_Case: 0805; SizeArea_mm2: 2.5; SizeAreaWB_mm2: 6.75; SizeX_mm: 2; SizeY_mm: 1.25; SizeZ_mm: 1.45; AEC Category: Q200; Green_Lifecycle: Active; Green_REACh: Passed
C155 C159 = GRM188R71H104KA93D: CAP, CERM, 0.1 µF, 50 V, +/- 10%, X7R, 0603; Manufacturer: MuRata; Polarized: N; CompType: Capacitor; Value: 0.1uF; U/M: EA; Cap_F: 0.0000001; Tolerance_%: 10; Value1: Unknown; VDC_V: 50; Value2: 50V; TaMin_C: -55; TaMax_C: 125; Cap_Case: 0603
C166 C168 = 06033C104JAT2A: CAP, CERM, 0.1uF, 25V, +/-5%, X7R, 0603; Manufacturer: AVX; Polarized: N; CompType: Capacitor; U/M: EA; Cap_F: 0.0000001; Tolerance_%: 5; ESR_Ohm: 0.05; Value1: 0.05 ohm; VDC_V: 25; TaMin_C: -55; TaMax_C: 125; Cap_Case: 0603
C169 = 06035A151JAT2A: CAP, CERM, 150 pF, 50 V, +/- 5%, C0G/NP0, 0603; Manufacturer: AVX; Polarized: N; CompType: Capacitor; Value: 150pF; U/M: EA; Cap_F: 0.00000000015; Tolerance_%: 5; ESR_ohm: 0.098; Value1: 0.098 ohm; VDC_V: 50; Value2: 50V; TaMin_C: -55; TaMax_C: 125; SizeArea_mm2: 1.28; SizeAreaWB_mm2: 4.68; SizeX_mm: 1.6; SizeY_mm: 0.8; SizeZ_mm: 1; AEC Category: Q200
J16 = 1751248: as J5 on sheet TIDA-010011-E1_Processor_Power _Pg7
R20 R38 R56 R57 R67 = RC0603FR-07100KL: RES, 100 k, 1%, 0.1 W, 0603; Manufacturer: Yageo America; CompType: Resistor; Value: 100k; Res_ohm: 100000; Tolerance_%: 1; Power_W: 0.1; Value2: 0.1W; VDC_V: 150; TempCo: 200 ppm/C; SizeArea_mm2: 1.28; SizeX_mm: 1.6; SizeY_mm: 0.8; EIA_Code: E96; U/M: EA; AEC Category: Q200; Green_Lifecycle: Active; Green_REACh: Passed
R54 = CRCW0402100KFKED: RES, 100 k, 1%, 0.063 W, 0402; Manufacturer: Vishay-Dale; CompType: Resistor; Value: 100k; Res_ohm: 100000; Tolerance_%: 1; Power_W: 0.063; Value2: 0.063W; VDC_V: 50; TempCo: 100 ppm/C; SizeArea_mm2: 0.5; SizeZ_mm: 0.6; EIA_Code: E96; U/M: EA; AEC Category: Q200; Green_Lifecycle: Active; Green_REACh: Passed
R55 R143-R145 = ERJ-3GEY0R00V: RES, 0, 5%, 0.1 W, 0603; Manufacturer: Panasonic; CompType: Resistor; Value: 0; Value_Code: 0000; Tolerance_%: 5; Power_W: 0.1; Value2: 0.1W; VDC_V: 50; TempCo: 600 ppm/C; SizeArea_mm2: 1.28; SizeX_mm: 1.6; SizeY_mm: 0.8; SizeZ_mm: 1; EIA_Code: E24; U/M: EA; AEC Category: Q200; Green_Lifecycle: Active; Green_REACh: Passed
R58 = CRCW06032K87FKEA: RES, 2.87 k, 1%, 0.1 W, 0603; Manufacturer: Vishay-Dale; CompType: Resistor; Value: 2.87k; Res_ohm: 2870; Value_Code: 2k87; Tolerance_%: 1; Power_W: 0.1; Value2: 0.1W; VDC_V: 75; TempCo: 100 ppm/C; SizeArea_mm2: 1.28; SizeX_mm: 1.6; SizeY_mm: 0.8; EIA_Code: E96; U/M: EA; AEC Category: Q200; Green_Lifecycle: Active; Green_REACh: Passed
R59 = CRCW06031K15FKEA: RES, 1.15 k, 1%, 0.1 W, 0603; Manufacturer: Vishay-Dale; CompType: Resistor; Value: 1.15k; Res_ohm: 1150; Value_Code: 1k15; Tolerance_%: 1; Power_W: 0.1; Value2: 0.1W; VDC_V: 75; TempCo: 100 ppm/C; SizeArea_mm2: 1.28; SizeX_mm: 1.6; SizeY_mm: 0.8; EIA_Code: E96; U/M: EA; AEC Category: Q200
R60 = CRCW0603681RFKEA: RES, 681, 1%, 0.1 W, 0603; Manufacturer: Vishay-Dale; CompType: Resistor; Value: 681; Value_Code: 681R; Tolerance_%: 1; Power_W: 0.1; Value2: 0.1W; VDC_V: 75; TempCo: 100 ppm/C; SizeArea_mm2: 1.28; SizeX_mm: 1.6; SizeY_mm: 0.8; EIA_Code: E96; U/M: EA; AEC Category: Q200; Green_Lifecycle: Active; Green_REACh: Passed
R61 = CRCW0603464RFKEA: RES, 464, 1%, 0.1 W, 0603; Manufacturer: Vishay-Dale; CompType: Resistor; Value: 464; Value_Code: 464R; Tolerance_%: 1; Power_W: 0.1; Value2: 0.1W; VDC_V: 75; TempCo: 100 ppm/C; SizeArea_mm2: 1.28; SizeX_mm: 1.6; SizeY_mm: 0.8; EIA_Code: E96; U/M: EA; AEC Category: Q200
R62 = CRCW0603113KFKEA: RES, 113 k, 1%, 0.1 W, 0603; Manufacturer: Vishay-Dale; CompType: Resistor; Value: 113k; Res_ohm: 113000; Tolerance_%: 1; Power_W: 0.1; Value2: 0.1W; VDC_V: 75; TempCo: 100 ppm/C; SizeArea_mm2: 1.28; SizeX_mm: 1.6; SizeY_mm: 0.8; EIA_Code: E96; U/M: EA; AEC Category: Q200; Green_Lifecycle: Active; Green_REACh: Passed
R63 = CRCW0603174KFKEA: RES, 174 k, 1%, 0.1 W, 0603; Manufacturer: Vishay-Dale; CompType: Resistor; Value: 174k; Res_ohm: 174000; Tolerance_%: 1; Power_W: 0.1; Value2: 0.1W; VDC_V: 75; TempCo: 100 ppm/C; SizeArea_mm2: 1.28; SizeX_mm: 1.6; SizeY_mm: 0.8; EIA_Code: E96; U/M: EA; AEC Category: Q200; Green_Lifecycle: Active; Green_REACh: Passed
R64 = CRCW0603348KFKEA: RES, 348 k, 1%, 0.1 W, 0603; Manufacturer: Vishay-Dale; CompType: Resistor; Value: 348k; Res_ohm: 348000; Tolerance_%: 1; Power_W: 0.1; Value2: 0.1W; VDC_V: 75; TempCo: 100 ppm/C; SizeArea_mm2: 1.28; SizeX_mm: 1.6; SizeY_mm: 0.8; EIA_Code: E96; U/M: EA; AEC Category: Q200; Green_Lifecycle: Active; Green_REACh: Passed
R65 = CRCW0603715KFKEA: RES, 715 k, 1%, 0.1 W, 0603; Manufacturer: Vishay-Dale; CompType: Resistor; Value: 715k; Res_ohm: 715000; Tolerance_%: 1; Power_W: 0.1; Value2: 0.1W; VDC_V: 75; TempCo: 100 ppm/C; SizeArea_mm2: 1.28; SizeX_mm: 1.6; SizeY_mm: 0.8; EIA_Code: E96; U/M: EA; AEC Category: Q200
R66 = CRCW06031M21FKEA: RES, 1.21 M, 1%, 0.1 W, 0603; Manufacturer: Vishay-Dale; CompType: Resistor; Value: 1.21Meg; Res_ohm: 1210000; Value_Code: 1M21; Tolerance_%: 1; Power_W: 0.1; Value2: 0.1W; VDC_V: 75; TempCo: 100 ppm/C; SizeArea_mm2: 1.28; SizeX_mm: 1.6; SizeY_mm: 0.8; EIA_Code: E96; U/M: EA; AEC Category: Q200; Green_Lifecycle: Active; Green_REACh: Passed
R125 = RT0603BRD0764K2L: RES, 64.2 k, 0.1%, 0.1 W, 0603; Manufacturer: Yageo America; CompType: Resistor; Value: 64.2k; Res_ohm: 64200; Value_Code: 64k2; Tolerance_%: 0.1; Value2: 0.1W; VDC_V: 75; TempCo: 25 ppm/C; SizeArea_mm2: 1.28; SizeX_mm: 1.6; SizeY_mm: 0.8; SizeZ_mm: 1; EIA_Code: E192; U/M: EA; AEC Category: Q200
R126 R129 R131 = ERJ-3EKF1002V: RES, 10.0 k, 1%, 0.1 W, 0603; Manufacturer: Panasonic; CompType: Resistor; Value: 10.0k; Res_ohm: 10000; Value_Code: 10k0; Tolerance_%: 1; Power_W: 0.1; Value2: 0.1W; VDC_V: 75; TempCo: 100 ppm/C; SizeArea_mm2: 1.28; SizeX_mm: 1.6; SizeY_mm: 0.8; EIA_Code: E96; U/M: EA; AEC Category: Q200; Green_Lifecycle: Active; Green_REACh: Passed
R127 = RG1608P-104-B-T5: RES, 100 k, 0.1%, 0.1 W, 0603; Manufacturer: Susumu Co Ltd; CompType: Resistor; Value: 100k; Res_ohm: 100000; Tolerance_%: 0.1; Value2: 0.1W; VDC_V: 75; TempCo: 25 ppm/C; SizeArea_mm2: 1.28; SizeX_mm: 1.6; SizeY_mm: 0.8; SizeZ_mm: 1; EIA_Code: E192; U/M: EA; AEC Category: Q200; Green_Lifecycle: Active; Green_REACh: Passed
R128 = CRCW060328K7FKEA: RES, 28.7 k, 1%, 0.1 W, 0603; Manufacturer: Vishay-Dale; CompType: Resistor; Value: 28.7k; Res_ohm: 28700; Value_Code: 28k7; Tolerance_%: 1; Power_W: 0.1; Value2: 0.1W; VDC_V: 75; TempCo: 100 ppm/C; SizeArea_mm2: 1.28; SizeX_mm: 1.6; SizeY_mm: 0.8; EIA_Code: E96; U/M: EA; AEC Category: Q200
R130 = RC0603FR-0747KL: RES, 47.0 k, 1%, 0.1 W, 0603; Manufacturer: Yageo America; CompType: Resistor; Value: 47.0k; Res_ohm: 47000; Value_Code: 47k0; Tolerance_%: 1; Power_W: 0.1; Value2: 0.1W; VDC_V: 150; TempCo: 200 ppm/C; SizeArea_mm2: 1.28; SizeX_mm: 1.6; SizeY_mm: 0.8; U/M: EA; AEC Category: Q200; Green_Lifecycle: Active; Green_REACh: Passed
R160 R162-R164 = CRCW040210K0FKED: RES, 10.0k ohm, 1%, 0.063W, 0402; Manufacturer: Vishay-Dale; CompType: Resistor; Res_ohm: 10000; Value_Code: 10k0; Tolerance_%: 1; Power_W: 0.063; VDC_V: 50; TempCo: 100 ppm/C; EIA_Code: E96; U/M: EA
R161 R165 = CRCW06030000Z0EA: RES, 0 ohm, 5%, 0.1W, 0603; Manufacturer: Vishay-Dale; CompType: Resistor; Value_Code: 0000; Tolerance_%: 5; Power_W: 0.1; VDC_V: 75; TempCo: 200 ppm/C; EIA_Code: E24; U/M: EA
R180 = CRCW08050000Z0EA: as R179 on sheet TIDA-010011-E1_Processor_Power _Pg7
S1 = CMP-0002193-2: Switch, SPST-NO, Off-Mom, 12 V, SMD; Manufacturer: Omron Electronic Components; CurrentRating_mA: 50A; PositionCount: 1; VDC_V: 12V
TP28 TP29 = 5000: as TP22 on sheet TIDA-010011-E1_Processor_Power _Pg7
TP30-TP34 TP54 TP70 TP79 = 5003: as TP24 on sheet TIDA-010011-E1_Processor_Power _Pg7
TP57 TP60 TP108 = 5000: as TP52 on sheet TIDA-010011-E1_Processor_Power _Pg7
TP58 TP59 TP61 = 5001: as TP53 on sheet TIDA-010011-E1_Processor_Power _Pg7
U19 = CMP-0035171-2: Dual Output LDO, 1 A, Fixed 1.8, 3.3 V Output, 2.7 to 10 V Input, 28-pin HTSSOP (PWP), -40 to 125 degC, Green (RoHS & no Sb/Br); Manufacturer: Texas Instruments; Vin(Min)(V): 2.7; Iout2(A): 1; Vin(Max)(V): 10; Vout2(Max)(V): 3.3; SubFamily: Dual Channel LDO; Iq(Typ)(mA): 0.08; Vdo(Typ)(mV): 350
U25 = CMP-0076409-1: SIMPLE SWITCHER(R) 2.95V to 6V, 4A Power Module in Small QFN package, RKG0039A (B1QFN-39); Manufacturer: Texas Instruments; Alternate PartNumber: LMZ30604RKGT; SizeAreaWB_mm2: 143.0; SizeArea_mm2: 99.0; SizeZ_mm: 2.9; SizeY_mm: 11.0; U/M: EA; CompType: IC; SizeX_mm: 9.0
U33 = CMP-0032418-2: Quad Voltage Supervisor with Manual Reset Input, DGK0008A (VSSOP-8); Manufacturer: Texas Instruments; Threshold Voltage 4 (typ)(Typ)(V): 0.4; Iq(Typ)(uA): 7; Time Delay(ms): 50; Rating: Catalog; SubFamily: Supervisor and Reset IC; Threshold Voltage 1 (typ)(Typ)(V): 2.9; VCC(Max)(V): 6.5; # of Supplies Monitored: 4; VCC(Min)(V): 1.8; AEC Category: Q200; AEC Qualified: N; CompType: IC; SizeAreaWB_mm2: 23.6; SizeArea_mm2: 14.7; SizeX_mm: 4.9; SizeY_mm: 3; SizeZ_mm: 1.1
U37 = CMP-0065454-1: 36-V Low-/High-Side Bi-Directional Zero-Drift Current Sense Amp w/Precision Int Shunt Resistor, PW0016A (TSSOP-16); Alternate Manufacturer: Texas Instruments; Green_Lifecycle: Active; SizeAreaWB_mm2: 58.8; Green_REACh: Passed; U/M: EA; SizeZ_mm: 1.2; SizeX_mm: 6.4; SizeY_mm: 5.0; SizeArea_mm2: 32.0; CompType: IC
U40 = CMP-0066662-2: 1.2V - 8V, 3A PFET High Side Load Switch w/ Level Shift & Adj Slew Rate Control, DDC0006A (SOT-23-T-6); Manufacturer: Texas Instruments; SizeZ_mm: 0.87; SizeX_mm: 1.65; SizeY_mm: 2.95; SizeArea_mm2: 4.8675; CompType: IC; U/M: EA; SizeAreaWB_mm2: 10.4675
U41 = TPS3808G01DBVR: Low Quiescent Current, Programmable-Delay Supervisory Circuit, DBV0006A (SOT-6); Alternate PartNumber: TPS3808G01DBVT; Manufacturer: Texas Instruments; SymbolCreator: Altium; SizeArea_mm2: 8.12; SizeAreaWB_mm2: 14.82; SizeX_mm: 2.8; SizeY_mm: 2.9; SizeZ_mm: 1.45; CompType: IC; U/M: EA

## Sheet TIDA-010011-E1_Processor_Power _Pg9.SchDoc: SWITCHING REGULATOR
size 431 x 279 mm; Date: Not shown in title block; ApprovedBy: Not shown in title block; CheckedBy: Not shown in title block; Author: Not shown in title block; CompanyName: Not shown in title block; DrawnBy: Sreenivasa; Engineer: Not shown in title block; Organization: Not shown in title block; Address1: Not shown in title block; Address2: Not shown in title block; Address3: Not shown in title block; Address4: Not shown in title block; DocumentNumber: 1; Revision: Use project parameter SCH_Rev; SheetNumber: 9; SheetTotal: 12; PageSetup: Record=PageOptions¦CenterHorizontal=True¦CenterVertical=True¦PrintScale=0.62¦XCorrection=1.00¦YCorrection=1.00¦PrintKind=0¦BorderSize=5000000¦LeftOffset=0¦BottomOffset=0¦Orientation=2¦PaperLength=1000¦PaperWidth=1000¦Scale=100¦PaperSource=15¦PrintQuality=600¦MediaType=1¦DitherType=10¦PrintScaleMode=1¦PaperKind=Letter
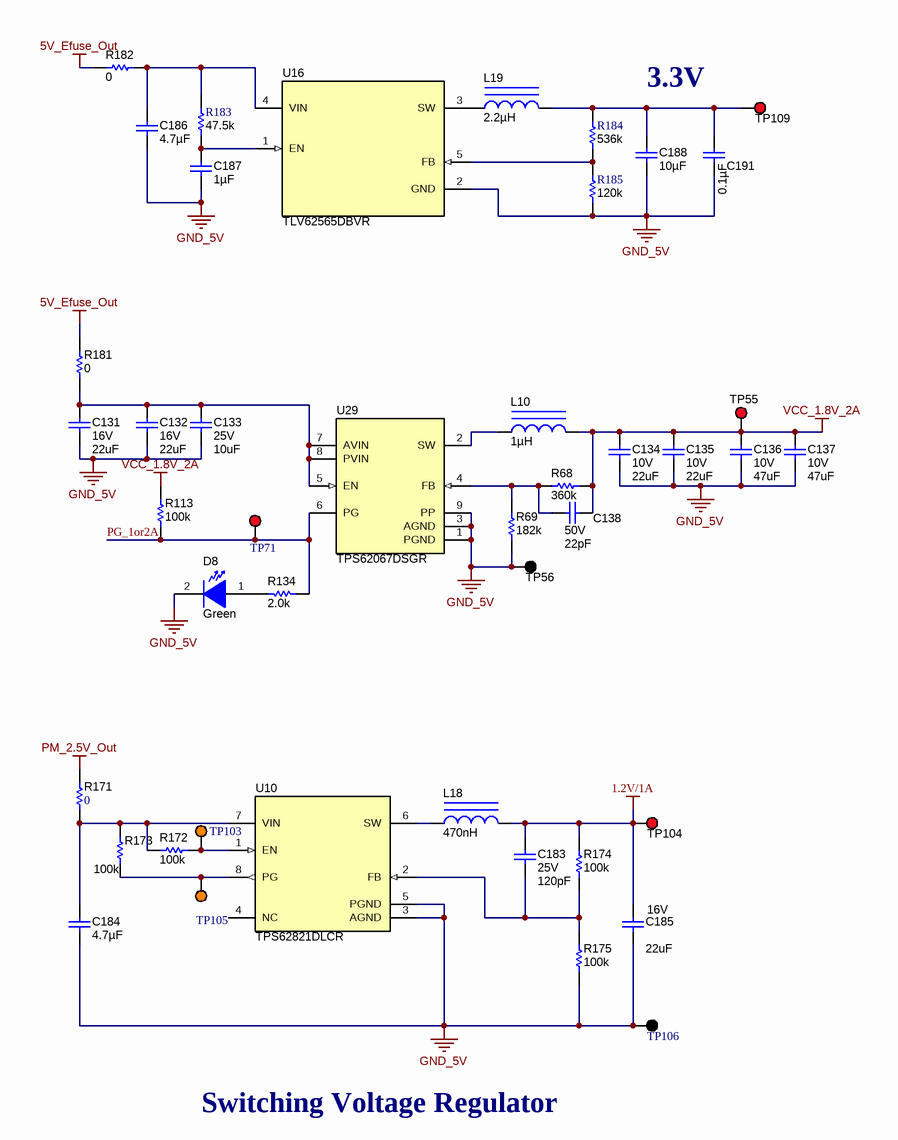
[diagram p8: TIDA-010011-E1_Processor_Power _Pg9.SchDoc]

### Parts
C131  VDC_V: 16V  ValueDisplayed: 22uF  [1210_280]  (hidden comment: C3225X7R1C226K250AC)
C132  VDC_V: 16V  ValueDisplayed: 22uF  [1210_280]  (hidden comment: C3225X7R1C226K250AC)
C133  VDC_V: 25V  ValueDisplayed: 10uF  [1206_190]  (hidden comment: C3216X7R1E106M160AE)
C134  VDC_V: 10V  ValueDisplayed: 22uF  [0805_HV]  (hidden comment: C2012X7S1A226M125AC)
C135  VDC_V: 10V  ValueDisplayed: 22uF  [0805_HV]  (hidden comment: C2012X7S1A226M125AC)
C136  VDC_V: 10V  ValueDisplayed: 47uF  [1210_270]  (hidden comment: GRM32ER71A476KE15L)
C137  VDC_V: 10V  ValueDisplayed: 47uF  [1210_270]  (hidden comment: GRM32ER71A476KE15L)
C138  VDC_V: 50V  ValueDisplayed: 22pF  [0402]  (hidden comment: GCM1555C1H220JA16D)
C183  VDC_V: 25V  ValueDisplayed: 120pF  [0201]  (hidden comment: GRM033R71E121KA01D)
C184  ValueDisplayed: 4.7µF  [0805_HV]  (hidden comment: C2012X7R1V475K125AC)
C185  VDC_V: 16V  ValueDisplayed: 22uF  [1206_190]  (hidden comment: EMK316BB7226ML-T)
C186  ValueDisplayed: 4.7µF  [0402]  (hidden comment: GRM155R60J475ME47D)
C187  ValueDisplayed: 1µF  [0805_HV]  (hidden comment: 08053D105KAT2A)
C188  ValueDisplayed: 10µF  [1210]  (hidden comment: GRM32ER71H106KA12L)
C191  ValueDisplayed: 0.1µF  [0603L]  (hidden comment: GRM188R71H104KA93D)
D8  value Green  [LED_LTST-C190_G]  (hidden comment: LTST-C190KGKT)
L10  ValueDisplayed: 1µH  [WE-PD2-S]  (hidden comment: 7447730)
L18  ValueDisplayed: 470nH  [XFL4015]  (hidden comment: XFL4015-471MEC)
L19  ValueDisplayed: 2.2µH  [WE-MAPI_2010]  (hidden comment: 74438343022)
R68  ValueDisplayed: 360k  [0402]  (hidden comment: CRCW0402360KFKED)
R69  ValueDisplayed: 182k  [0402]  (hidden comment: CRCW0402182KFKED)
R113  ValueDisplayed: 100k  [0402]  (hidden comment: CRCW0402100KJNED)
R134  ValueDisplayed: 2.0k  [0603]  (hidden comment: CRCW06032K00JNEA)
R171  ValueDisplayed: 0  [0805_HV]  (hidden comment: ERJ-6GEY0R00V)
R172  ValueDisplayed: 100k  [0603]  (hidden comment: ERA-3AEB104V)
R173  ValueDisplayed: 100k  [0603]  (hidden comment: ERA-3AEB104V)
R174  ValueDisplayed: 100k  [0603]  (hidden comment: ERA-3AEB104V)
R175  ValueDisplayed: 100k  [0603]  (hidden comment: ERA-3AEB104V)
R181  ValueDisplayed: 0  [0805_HV]  (hidden comment: CRCW08050000Z0EA)
R182  ValueDisplayed: 0  [0805_HV]  (hidden comment: CRCW08050000Z0EA)
R183  value 47.5k  [0603]  (hidden comment: RT0603DRE07976RL)
R184  value 536k  [0603]  (hidden comment: RT0603DRE07976RL)
R185  value 120k  [0603]  (hidden comment: RT0603DRE07976RL)
TP55  5000  [Keystone5000]  (value not drawn)
TP56  5001  [Keystone5001]  (value not drawn)
TP71  5000  [Keystone5000]  (value not drawn)
TP103  5003  [Keystone5003]  (value not drawn)
TP104  (no value)  [Keystone5000]
TP105  5003  [Keystone5003]  (value not drawn)
TP106  5001  [Keystone5001]  (value not drawn)
TP109  5000  [Keystone5000]  (value not drawn)
U10  TPS62821DLCR  [DLC0008A]
U16  TLV62565DBVR  [DBV0005A_N]
U29  TPS62067DSGR  [DSG0008A]

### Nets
1.2V/1A: C183.1 C185.1 L18.2 R174.2 TP104.1
5V_Efuse_Out: R181.1 R182.2
GND_5V: C131.2 C132.2 C133.2 C134.2 C135.2 C136.2 C137.2 C184.2 C185.2 C186.2 C187.2 C188.2 C191.1 D8.2(K) R69.1 R175.1 R185.1 TP56.1 TP106.1 U10.3(AGND) U10.5(PGND) U16.2(GND) U29.1(PGND) U29.3(AGND) U29.9(PP)
PM_2.5V_Out: R171.1
VCC_1.8V_2A: C134.1 C135.1 C136.1 C137.1 C138.1 L10.2 R68.2 R113.1 TP55.1
PG_1or2A: R113.2 R134.1 TP71.1 U29.6(PG)
NetC131_1: C131.1 C132.1 C133.1 R181.2 U29.5(EN) U29.7(AVIN) U29.8(PVIN)
NetC138_2: C138.2 R68.1 R69.2 U29.4(FB)
NetC183_2: C183.2 R174.1 R175.2 U10.2(FB)
NetC184_1: C184.1 R171.2 R172.1 R173.1 U10.7(VIN)
NetC186_1: C186.1 R182.1 R183.2 U16.4(VIN)
NetC187_1: C187.1 R183.1 U16.1(EN)
NetC188_1: C188.1 C191.2 L19.2 R184.2 TP109.1
NetD8_1: D8.1(A) R134.2
NetL10_1: L10.1 U29.2(SW)
NetL18_1: L18.1 U10.6(SW)
NetL19_1: L19.1 U16.3(SW)
NetR172_2: R172.2 TP103.1 U10.1(EN)
NetR173_2: R173.2 TP105.1 U10.8(PG)
NetR184_1: R184.1 R185.2 U16.5(FB)

Not connected (* = marked no-connect by the designer): U10 4(NC)

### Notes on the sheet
- 3.3V
- Switching Voltage Regulator

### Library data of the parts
C131 C132 = CMP-0009116-1: CAP, CERM, 22 uF, 16 V, +/- 10%, X7R, 1210; Manufacturer: TDK; TaMin_C: -55°C; ESR_ohm: 2.582m; Polarized: N; SizeAreaWB_mm2: 14.7; Value1: 0.002582 ohm; U/M: EA; Value: 22uF; TaMax_C: 125°C; SizeZ_mm: 2.8; SizeX_mm: 3.2; SizeY_mm: 2.5; SizeArea_mm2: 8; Cap_F: 22µF; IRMS_A: 4.57562A; AEC Category: Q200
C133 = CMP-0008692-2: CAP, CERM, 10 uF, 25 V, +/- 20%, X7R, 1206_190; Manufacturer: TDK; TaMin_C: -55°C; Polarized: N; SizeAreaWB_mm2: 10.92; Value1: Unknown; U/M: EA; Value: 10uF; TaMax_C: 125°C; SizeZ_mm: 1.9; SizeX_mm: 3.2; SizeY_mm: 1.6; Cap_Case: 1206; SizeArea_mm2: 5.12; CompType: Capacitor; Cap_F: 10µF; AEC Category: Q200
C134 C135 = CMP-0007890-2: CAP, CERM, 22 uF, 10 V, +/- 20%, X7S, 0805; Manufacturer: TDK; TaMin_C: -55°C; ESR_ohm: 2.05m; Polarized: N; SizeAreaWB_mm2: 6.75; Value1: 0.00205 ohm; U/M: EA; Value: 22uF; TaMax_C: 125°C; SizeZ_mm: 1.45; SizeX_mm: 2; SizeY_mm: 1.25; Cap_Case: 0805; SizeArea_mm2: 2.5; Cap_F: 22µF; IRMS_A: 4.55587A; AEC Category: Q200
C136 C137 = CMP-0009220-2: CAP, CERM, 47 uF, 10 V, +/- 10%, X7R, 1210; Manufacturer: MuRata; TaMin_C: -55°C; Polarized: N; SizeAreaWB_mm2: 14.7; Value1: Unknown; U/M: EA; Value: 47uF; TaMax_C: 125°C; SizeZ_mm: 2.7; SizeX_mm: 3.2; SizeY_mm: 2.5; Cap_Case: 1210; SizeArea_mm2: 8; Cap_F: 47µF; AEC Category: Q200
C138 = CMP-0006348-2: CAP, CERM, 22 pF, 50 V, +/- 5%, C0G/NP0, AEC-Q200 Grade 1, 0402; Manufacturer: MuRata; TaMin_C: -55°C; Polarized: N; SizeAreaWB_mm2: 3; Value1: Unknown; U/M: EA; Value: 22pF; TaMax_C: 125°C; SizeZ_mm: 0.6; SizeX_mm: 1; SizeY_mm: 0.5; AEC Qualified: Y; AEC Category: Q200
C183 = CMP-0009765-1: CAP, CERM, 120 pF, 25 V, +/- 10%, X7R, 0201; Manufacturer: MuRata; TaMin_C: -55°C; Polarized: N; SizeAreaWB_mm2: 2.08; Value1: Unknown; U/M: EA; Value: 120pF; TaMax_C: 125°C; SizeZ_mm: 0.26; SizeX_mm: 0.6; SizeY_mm: 0.3; SizeArea_mm2: 0.18; AEC Category: Q200
C184 = C2012X7R1V475K125AC: CAP, CERM, 4.7 µF, 35 V, +/- 10%, X7R, 0805; Manufacturer: TDK; Polarized: N; CompType: Capacitor; Value: 4.7uF; U/M: EA; Cap_F: 0.0000047; Tolerance_%: 10; ESR_ohm: 0.002346; Value1: 0.002346 ohm; VDC_V: 35; Value2: 35V; IRMS_A: 4.26021; TaMin_C: -55; TaMax_C: 125; Cap_Case: 0805; AEC Category: Q200; SizeArea_mm2: 2.5; SizeAreaWB_mm2: 6.75; SizeX_mm: 2; SizeY_mm: 1.25; SizeZ_mm: 1.45
C185 = CMP-0008805-2: CAP, CERM, 22 uF, 16 V, +/- 20%, X7R, 1206_190; Manufacturer: Taiyo Yuden; TaMin_C: -55°C; Polarized: N; SizeAreaWB_mm2: 10.92; Value1: Unknown; U/M: EA; Value: 22uF; TaMax_C: 125°C; SizeZ_mm: 1.9; SizeX_mm: 3.2; SizeY_mm: 1.6; Cap_Case: 1206; SizeArea_mm2: 5.12; Cap_F: 22µF; AEC Category: Q200
C186 = GRM155R60J475ME47D: CAP, CERM, 4.7 µF, 6.3 V,+/- 20%, X5R, 0402; Manufacturer: MuRata; Polarized: N; CompType: Capacitor; Value: 4.7uF; U/M: EA; Cap_F: 0.0000047; Tolerance_%: 20; VDC_V: 6.3; Value2: 6.3V; TaMin_C: -55; TaMax_C: 85; SizeArea_mm2: 0.5; SizeAreaWB_mm2: 3; SizeX_mm: 1; SizeZ_mm: 0.6; AEC Category: Q200; Green_Lifecycle: Active; Green_REACh: Passed
C187 = 08053D105KAT2A: as C65 on sheet TIDA-010011-E1_Processor_Power _Pg7
C188 = GRM32ER71H106KA12L: CAP, CERM, 10 µF, 50 V, +/- 10%, X7R, 1210; Manufacturer: MuRata; Polarized: N; CompType: Capacitor; Value: 10uF; U/M: EA; Cap_F: 0.00001; Tolerance_%: 10; Value1: Unknown; VDC_V: 50; Value2: 50V; TaMin_C: -55; TaMax_C: 125
C191 = GRM188R71H104KA93D: as C155 on sheet TIDA-010011-E1_Processor_Power _Pg8
D8 = LTST-C190KGKT: LED, Green, SMD; Manufacturer: Lite-On; Type: AlInGaP; Vf_V: 2; Value2: 2V; Io_A: 0.03; Tjmax_C: 85; Value1: W; U/M: EA
L10 = 7447730: Inductor, Shielded Drum Core, Ferrite, 1 µH, 4 A, 0.049 ohm, SMD; Manufacturer: Wurth Elektronik; Value: 1uH; Ind_H: 1.0E-6; Imax_A: 4; Irms: 4A @ 40C rise; Isat: 5.72A @ 10% inductance drop; DCR_ohm: 0.049; Value2: 4A; SizeAreaWB_mm2: 27.5; SizeArea_mm2: 18; SizeY_mm: 4.5; SizeZ_mm: 3.2; AEC Category: Q200; Green_Lifecycle: Active; Green_REACh: Passed
L18 = CMP-0061147-1: Inductor, Shielded, Composite, 470 nH, 3.5 A, 0.0076 ohm, SMD; Manufacturer: Coilcraft; Isat: 3.5A @ 10% inductance drop; Irms: 9.1A @ 20C rise; Green_Lifecycle: Not Set; SizeAreaWB_mm2: 28.09; DCR_ohm: 7.6m; Green_REACh: Incomplete; Value: 470nH; Imax_A: 3.5A; SizeZ_mm: 1.6; SizeX_mm: 4.3; SizeArea_mm2: 18.49; AEC Category: Q200
L19 = 74438343022: Inductor, Shielded, 2.2 µH, 1.1 A, 0.27 ohm, SMD; Manufacturer: Wurth Elektronik; Value: 2.2uH; Ind_H: 2.2E-6; Imax_A: 1.1; Irms: 1.1A @ 40C rise; Isat: 2.5A @ 20% inductance drop; DCR_ohm: 0.27; Value2: 1.1A; SizeAreaWB_mm2: 7.8; SizeArea_mm2: 3.2; SizeX_mm: 2; SizeY_mm: 1.6; SizeZ_mm: 1; AEC Category: Q200; AEC Qualified: N
R68 = CRCW0402360KFKED: RES, 360 k, 1%, 0.063 W, AEC-Q200 Grade 0, 0402; Manufacturer: Vishay-Dale; CompType: Resistor; Value: 360k; Res_ohm: 360000; Tolerance_%: 1; Power_W: 0.063; Value2: 0.063W; VDC_V: 50; TempCo: 100 ppm/C; SizeArea_mm2: 0.5; SizeZ_mm: 0.6; U/M: EA; AEC Category: Q200; AEC Qualified: Y; AEC Grade: 0
R69 = CRCW0402182KFKED: RES, 182 k, 1%, 0.063 W, 0402; Manufacturer: Vishay-Dale; CompType: Resistor; Value: 182k; Res_ohm: 182000; Tolerance_%: 1; Power_W: 0.063; Value2: 0.063W; VDC_V: 50; TempCo: 100 ppm/C; SizeArea_mm2: 0.5; SizeZ_mm: 0.6; EIA_Code: E96; U/M: EA; AEC Category: Q200; Green_Lifecycle: Active; Green_REACh: Passed
R113 = CMP-0026823-2: RES, 100 k, 5%, 0.063 W, 0402; Manufacturer: Vishay-Dale; Power_W: 63mW; TempCo: 200 ppm/C; U/M: EA; Value: 100k; EIA_Code: E24; SizeX_mm: 1; SizeY_mm: 0.5; SizeZ_mm: 0.6; Value2: 0.063W; VDC_V: 50V; AEC Category: Q200
R134 = CRCW06032K00JNEA: RES, 2.0 k, 5%, 0.1 W, 0603; Manufacturer: Vishay-Dale; CompType: Resistor; Value: 2.0k; Res_ohm: 2000; Value_Code: 2k00; Tolerance_%: 5; Power_W: 0.1; Value2: 0.1W; VDC_V: 75; TempCo: 200 ppm/C; SizeArea_mm2: 1.28; SizeX_mm: 1.6; SizeY_mm: 0.8; SizeZ_mm: 1; EIA_Code: E24; U/M: EA; AEC Category: Q200; Green_Lifecycle: Active; Green_REACh: Passed
R171 = CMP-0020616-3: RES, 0, 5%, 0.125 W, AEC-Q200 Grade 0, 0805; Manufacturer: Panasonic; Power_W: 125mW; TempCo: 600 ppm/C; Value_Code: 0000; Value: 0; EIA_Code: E24; SizeX_mm: 2; SizeY_mm: 1.25; SizeZ_mm: 1.45; Value2: 0.125W; SizeArea_mm2: 2.5; AEC Qualified: Y; VDC_V: 150V; AEC Category: Q200; SizeAreaWB_mm2: 6.75
R172-R175 = CMP-0023363-3: RES, 100 k, 0.1%, 0.1 W, AEC-Q200 Grade 0, 0603; Manufacturer: Panasonic; Power_W: 100mW; TempCo: 25 ppm/C; U/M: EA; Value: 100k; EIA_Code: E192; SizeX_mm: 1.6; SizeY_mm: 0.8; SizeZ_mm: 1; Value2: 0.1W; SizeArea_mm2: 1.28; AEC Qualified: Y; VDC_V: 75V; AEC Grade: 0; AEC Category: Q200
R181 R182 = CRCW08050000Z0EA: as R179 on sheet TIDA-010011-E1_Processor_Power _Pg7
R183-R185 = RT0603DRE07976RL: RES, 976 ohm, 0.5%, 0.1W, 0603; Manufacturer: Yageo America; CompType: Resistor; Res_ohm: 976; Value_Code: 976R; Tolerance_%: 0.5; Power_W: 0.1; VDC_V: 75; TempCo: 50 ppm/C; EIA_Code: E192; U/M: EA
TP55 TP109 = 5000: Test Point, Miniature, Red, TH; Manufacturer: Keystone; CompType: Test Point Loop; U/M: EA
TP56 = 5001: Test Point, Miniature, Black, TH; Manufacturer: Keystone; CompType: Test Point Loop; U/M: EA
TP71 = 5000: as TP22 on sheet TIDA-010011-E1_Processor_Power _Pg7
TP103 TP105 = 5003: as TP24 on sheet TIDA-010011-E1_Processor_Power _Pg7
TP104 = 5000: as TP52 on sheet TIDA-010011-E1_Processor_Power _Pg7
TP106 = 5001: as TP53 on sheet TIDA-010011-E1_Processor_Power _Pg7
U10 = CMP-0065148-3: 1A Step-Down Converter With 1% Accuracy, DLC0008A (VSON-HR-8); Manufacturer: Texas Instruments; SizeX_mm: 1.5; SizeY_mm: 2.0; CompType: IC; SizeZ_mm: 1.0; SizeArea_mm2: 3.0; SizeAreaWB_mm2: 7.5; AEC Category: Q200; AEC Qualified: N
U16 = CMP-0067005-1: 1.5A Buck Converter in SOT23 Package, DBV0005A (SOT-23-5); Alternate PartNumber: TLV62565DBVT; Alternate Manufacturer: Texas Instruments; Green_Lifecycle: Active; SizeAreaWB_mm2: 14.82; Green_REACh: Passed; U/M: EA; SizeZ_mm: 1.45; SizeX_mm: 2.8; SizeY_mm: 2.9; SizeArea_mm2: 8.12; CompType: IC
U29 = CMP-0037738-2: Buck Step Down Regulator with 2.9 to 6 V Input and 0.8 to 6 V Output, -40 to 85 degC, 8-Pin WSON (DSG), Green (RoHS & no Sb/Br); Manufacturer: Texas Instruments; Vin(Min)(V): 2.9; Switch Current Limit(Typ)(A): 2.75; Vin(Max)(V): 6; Rating: Catalog; Vout(Min)(V): 0.8; Duty Cycle(Max)(%): 100; Regulated Outputs(#): 1; SubFamily: Step-Down Regulator; Synchronous Rectification: TRUE; Iq(Typ)(mA): 0.018; Iout(Max)(A): 2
